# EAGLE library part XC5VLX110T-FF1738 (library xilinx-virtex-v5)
xc5vlx110t_ff1738 edit this description Auto generated by make-symbol-device-package-bsdl.ulp Rev. 21 Source: xc5vlx110t_ff1738.bsd Connect-List generated from XC5VLX110T_FF1738.DEV Variant '' with split-device-symbol.ulp
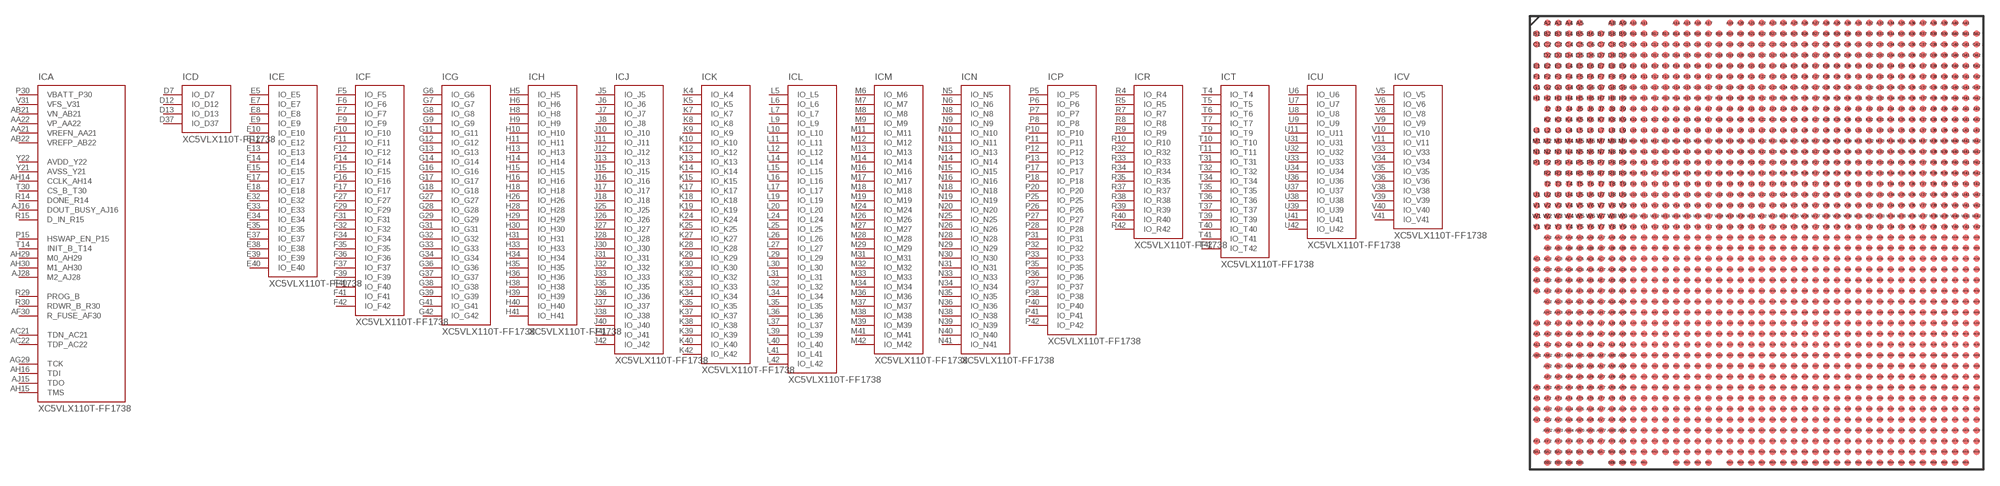
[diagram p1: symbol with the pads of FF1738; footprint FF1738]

Designator prefix IC; gates A=XC5VLX110T_FF1738-CONTROL D=XC5VLX110T_FF1738-IO-D E=XC5VLX110T_FF1738-IO-E F=XC5VLX110T_FF1738-IO-F G=XC5VLX110T_FF1738-IO-G H=XC5VLX110T_FF1738-IO-H J=XC5VLX110T_FF1738-IO-J K=XC5VLX110T_FF1738-IO-K L=XC5VLX110T_FF1738-IO-L M=XC5VLX110T_FF1738-IO-M N=XC5VLX110T_FF1738-IO-N P=XC5VLX110T_FF1738-IO-P R=XC5VLX110T_FF1738-IO-R T=XC5VLX110T_FF1738-IO-T U=XC5VLX110T_FF1738-IO-U V=XC5VLX110T_FF1738-IO-V W=XC5VLX110T_FF1738-IO-W Y=XC5VLX110T_FF1738-IO-Y AA=XC5VLX110T_FF1738-IO-AA AB=XC5VLX110T_FF1738-IO-AB AC=XC5VLX110T_FF1738-IO-AC AD=XC5VLX110T_FF1738-IO-AD AE=XC5VLX110T_FF1738-IO-AE AF=XC5VLX110T_FF1738-IO-AF AG=XC5VLX110T_FF1738-IO-AG AH=XC5VLX110T_FF1738-IO-AH AJ=XC5VLX110T_FF1738-IO-AJ AK=XC5VLX110T_FF1738-IO-AK AL=XC5VLX110T_FF1738-IO-AL AM=XC5VLX110T_FF1738-IO-AM AN=XC5VLX110T_FF1738-IO-AN AP=XC5VLX110T_FF1738-IO-AP AR=XC5VLX110T_FF1738-IO-AR AT=XC5VLX110T_FF1738-IO-AT AU=XC5VLX110T_FF1738-IO-AU AV=XC5VLX110T_FF1738-IO-AV MGTAVTTRX=XC5VLX110T_FF1738-MGTAVTTRX MGREFCLKN=XC5VLX110T_FF1738-MGTREFCLKN MGRX=XC5VLX110T_FF1738-MGTRX MGTTRXN=XC5VLX110T_FF1738-MGTTXN VCCINT=XC5VLX110T_FF1738-VCCINT VCCO=XC5VLX110T_FF1738-VCCO VCCAUX=XC5VLX110T_FF1738-VCCAUX MGTAVCC=XC5VLX110T_FF1738-MGTAVCC MGTAVCCPLL=XC5VLX110T_FF1738-MGTAVCCPLL GND=XC5VLX110T_FF1738-GND NC=XC5VLX110T_FF1738-NOCONNECT

## XC5VLX110T-FF1738 (OC_FARNELL: unknown; OC_NEWARK: unknown)  [FF1738]
A2  MGRX:MGTRXP1_124  pas
A3  MGRX:MGTRXN1_124  pas
A4  MGRX:MGTRXN0_124  pas
A5  MGRX:MGTRXP0_124  pas
A8  NC:NOCONNECT1  pas
A9  NC:NOCONNECT2  pas
A10  NC:NOCONNECT3  pas
A11  NC:NOCONNECT4  pas
A14  NC:NOCONNECT5  pas
A15  NC:NOCONNECT6  pas
A16  NC:NOCONNECT7  pas
A17  NC:NOCONNECT8  pas
A19  GND:GND  pwr
A20  NC:NOCONNECT9  pas
A21  NC:NOCONNECT10  pas
A22  NC:NOCONNECT11  pas
A23  GND:GND  pwr
A24  NC:NOCONNECT12  pas
A25  NC:NOCONNECT13  pas
A26  NC:NOCONNECT14  pas
A27  NC:NOCONNECT15  pas
A28  GND:GND  pwr
A29  NC:NOCONNECT16  pas
A30  NC:NOCONNECT17  pas
A31  NC:NOCONNECT18  pas
A32  NC:NOCONNECT19  pas
A33  GND:GND  pwr
A34  NC:NOCONNECT20  pas
A35  NC:NOCONNECT21  pas
A36  NC:NOCONNECT22  pas
A37  NC:NOCONNECT23  pas
A38  GND:GND  pwr
A39  NC:NOCONNECT24  pas
A40  NC:NOCONNECT25  pas
A41  NC:NOCONNECT26  pas
AA2  MGTTRXN:MGTTXP1_112  pas
AA3  MGTAVTTRX:MGTAVTTTX_1122  pas
AA4  NC:NOCONNECT150  pas
AA5  MGTAVTTRX:MGTAVTTRXC  pas
AA6  AA:IO_AA6
AA7  AA:IO_AA7
AA8  VCCO:VCCO12  pwr
AA9  AA:IO_AA9
AA10  AA:IO_AA10
AA11  AA:IO_AA11
AA12  VCCAUX:VCCAUX  pwr
AA13  GND:GND  pwr
AA14  VCCINT:VCCINT  pwr
AA15  GND:GND  pwr
AA16  VCCINT:VCCINT  pwr
AA17  GND:GND  pwr
AA18  VCCINT:VCCINT  pwr
AA19  GND:GND  pwr
AA20  VCCINT:VCCINT  pwr
AA21  A:VREFN_AA21  pas
AA22  A:VP_AA22  pas
AA23  GND:GND  pwr
AA24  VCCINT:VCCINT  pwr
AA25  GND:GND  pwr
AA26  VCCINT:VCCINT  pwr
AA27  GND:GND  pwr
AA28  VCCINT:VCCINT  pwr
AA29  GND:GND  pwr
AA30  VCCAUX:VCCAUX  pwr
AA31  GND:GND  pwr
AA32  AA:IO_AA32
AA33  GND:GND  pwr
AA34  AA:IO_AA34
AA35  AA:IO_AA35
AA36  AA:IO_AA36
AA37  AA:IO_AA37
AA38  VCCO:VCCO11  pwr
AA39  AA:IO_AA39
AA40  AA:IO_AA40
AA41  AA:IO_AA41
AA42  AA:IO_AA42
AB2  MGTTRXN:MGTTXP0_114  pas
AB3  MGTAVTTRX:MGTAVTTTX_1141  pas
AB4  MGREFCLKN:MGTRREF_112  pas
AB5  GND:GND  pwr
AB6  AB:IO_AB6
AB7  AB:IO_AB7
AB8  AB:IO_AB8
AB9  AB:IO_AB9
AB10  GND:GND  pwr
AB11  AB:IO_AB11
AB12  GND:GND  pwr
AB13  VCCINT:VCCINT  pwr
AB14  GND:GND  pwr
AB15  VCCINT:VCCINT  pwr
AB16  GND:GND  pwr
AB17  VCCINT:VCCINT  pwr
AB18  GND:GND  pwr
AB19  VCCINT:VCCINT  pwr
AB20  GND:GND  pwr
AB21  A:VN_AB21  pas
AB22  A:VREFP_AB22  pas
AB23  VCCINT:VCCINT  pwr
AB24  GND:GND  pwr
AB25  VCCINT:VCCINT  pwr
AB26  GND:GND  pwr
AB27  VCCINT:VCCINT  pwr
AB28  GND:GND  pwr
AB29  VCCINT:VCCINT  pwr
AB30  GND:GND  pwr
AB31  VCCAUX:VCCAUX  pwr
AB32  AB:IO_AB32
AB33  AB:IO_AB33
AB34  AB:IO_AB34
AB35  VCCO:VCCO13  pwr
AB36  AB:IO_AB36
AB37  AB:IO_AB37
AB38  AB:IO_AB38
AB39  AB:IO_AB39
AB40  GND:GND  pwr
AB41  AB:IO_AB41
AB42  AB:IO_AB42
AC1  MGRX:MGTRXP0_114  pas
AC2  MGTTRXN:MGTTXN0_114  pas
AC3  MGTAVTTRX:MGTAVTTRX_114  pas
AC4  GND:GND  pwr
AC5  AC:IO_AC5
AC6  AC:IO_AC6
AC7  GND:GND  pwr
AC8  AC:IO_AC8
AC9  AC:IO_AC9
AC10  AC:IO_AC10
AC11  GND:GND  pwr
AC12  VCCAUX:VCCAUX  pwr
AC13  GND:GND  pwr
AC14  VCCINT:VCCINT  pwr
AC15  GND:GND  pwr
AC16  VCCINT:VCCINT  pwr
AC17  GND:GND  pwr
AC18  VCCINT:VCCINT  pwr
AC19  GND:GND  pwr
AC20  VCCINT:VCCINT  pwr
AC21  A:TDN_AC21  pas
AC22  A:TDP_AC22  pas
AC23  GND:GND  pwr
AC24  VCCINT:VCCINT  pwr
AC25  GND:GND  pwr
AC26  VCCINT:VCCINT  pwr
AC27  GND:GND  pwr
AC28  VCCINT:VCCINT  pwr
AC29  GND:GND  pwr
AC30  VCCAUX:VCCAUX  pwr
AC31  GND:GND  pwr
AC32  GND:GND  pwr
AC33  AC:IO_AC33
AC34  AC:IO_AC34
AC35  AC:IO_AC35
AC36  AC:IO_AC36
AC37  GND:GND  pwr
AC38  AC:IO_AC38
AC39  AC:IO_AC39
AC40  AC:IO_AC40
AC41  AC:IO_AC41
AC42  GND:GND  pwr
AD1  MGRX:MGTRXN0_114  pas
AD2  GND:GND  pwr
AD3  MGREFCLKN:MGTREFCLKN_114  pas
AD4  MGREFCLKN:MGTREFCLKP_114  pas
AD5  AD:IO_AD5
AD6  AD:IO_AD6
AD7  AD:IO_AD7
AD8  AD:IO_AD8
AD9  VCCO:VCCO18  pwr
AD10  AD:IO_AD10
AD11  AD:IO_AD11
AD12  GND:GND  pwr
AD13  VCCINT:VCCINT  pwr
AD14  GND:GND  pwr
AD15  VCCINT:VCCINT  pwr
AD16  GND:GND  pwr
AD17  VCCINT:VCCINT  pwr
AD18  GND:GND  pwr
AD19  VCCINT:VCCINT  pwr
AD20  GND:GND  pwr
AD21  VCCINT:VCCINT  pwr
AD22  GND:GND  pwr
AD23  VCCINT:VCCINT  pwr
AD24  GND:GND  pwr
AD25  VCCINT:VCCINT  pwr
AD26  GND:GND  pwr
AD27  VCCINT:VCCINT  pwr
AD28  GND:GND  pwr
AD29  VCCINT:VCCINT  pwr
AD30  GND:GND  pwr
AD31  VCCAUX:VCCAUX  pwr
AD32  AD:IO_AD32
AD33  AD:IO_AD33
AD34  GND:GND  pwr
AD35  AD:IO_AD35
AD36  AD:IO_AD36
AD37  AD:IO_AD37
AD38  AD:IO_AD38
AD39  VCCO:VCCO13  pwr
AD40  AD:IO_AD40
AD41  AD:IO_AD41
AD42  AD:IO_AD42
AE1  MGRX:MGTRXN1_114  pas
AE2  GND:GND  pwr
AE3  MGTAVCC:MGTAVCC_114  pwr
AE4  MGTAVCC:MGTAVCC_114  pwr
AE5  AE:IO_AE5
AE6  VCCO:VCCO18  pwr
AE7  AE:IO_AE7
AE8  AE:IO_AE8
AE9  AE:IO_AE9
AE10  AE:IO_AE10
AE11  GND:GND  pwr
AE12  VCCAUX:VCCAUX  pwr
AE13  GND:GND  pwr
AE14  VCCINT:VCCINT  pwr
AE15  GND:GND  pwr
AE16  VCCINT:VCCINT  pwr
AE17  GND:GND  pwr
AE18  VCCINT:VCCINT  pwr
AE19  GND:GND  pwr
AE20  VCCINT:VCCINT  pwr
AE21  GND:GND  pwr
AE22  VCCINT:VCCINT  pwr
AE23  GND:GND  pwr
AE24  VCCINT:VCCINT  pwr
AE25  GND:GND  pwr
AE26  VCCINT:VCCINT  pwr
AE27  GND:GND  pwr
AE28  VCCINT:VCCINT  pwr
AE29  GND:GND  pwr
AE30  VCCAUX:VCCAUX  pwr
AE31  GND:GND  pwr
AE32  AE:IO_AE32
AE33  AE:IO_AE33
AE34  AE:IO_AE34
AE35  AE:IO_AE35
AE36  VCCO:VCCO13  pwr
AE37  AE:IO_AE37
AE38  AE:IO_AE38
AE39  AE:IO_AE39
AE40  AE:IO_AE40
AE41  GND:GND  pwr
AE42  AE:IO_AE42
AF1  MGRX:MGTRXP1_114  pas
AF2  MGTTRXN:MGTTXN1_114  pas
AF3  MGTAVCCPLL:MGTAVCCPLL_114  pwr
AF4  GND:GND  pwr
AF5  AF:IO_AF5
AF6  AF:IO_AF6
AF7  AF:IO_AF7
AF8  GND:GND  pwr
AF9  AF:IO_AF9
AF10  AF:IO_AF10
AF11  AF:IO_AF11
AF12  AF:IO_AF12
AF13  VCCAUX:VCCAUX  pwr
AF14  GND:GND  pwr
AF15  VCCINT:VCCINT  pwr
AF16  GND:GND  pwr
AF17  VCCINT:VCCINT  pwr
AF18  GND:GND  pwr
AF19  VCCINT:VCCINT  pwr
AF20  GND:GND  pwr
AF21  VCCINT:VCCINT  pwr
AF22  GND:GND  pwr
AF23  VCCINT:VCCINT  pwr
AF24  GND:GND  pwr
AF25  VCCINT:VCCINT  pwr
AF26  GND:GND  pwr
AF27  VCCINT:VCCINT  pwr
AF28  GND:GND  pwr
AF29  VCCAUX:VCCAUX  pwr
AF30  A:R_FUSE_AF30  pas
AF31  AF:IO_AF31
AF32  AF:IO_AF32
AF33  GND:GND  pwr
AF34  AF:IO_AF34
AF35  AF:IO_AF35
AF36  AF:IO_AF36
AF37  AF:IO_AF37
AF38  GND:GND  pwr
AF39  AF:IO_AF39
AF40  AF:IO_AF40
AF41  AF:IO_AF41
AF42  AF:IO_AF42
AG2  MGTTRXN:MGTTXP1_114  pas
AG3  MGTAVTTRX:MGTAVTTTX_1142  pas
AG4  AG:IO_AG4
AG5  GND:GND  pwr
AG6  AG:IO_AG6
AG7  AG:IO_AG7
AG8  AG:IO_AG8
AG9  AG:IO_AG9
AG10  VCCO:VCCO18  pwr
AG11  AG:IO_AG11
AG12  AG:IO_AG12
AG13  GND:GND  pwr
AG14  VCCINT:VCCINT  pwr
AG15  GND:GND  pwr
AG16  VCCINT:VCCINT  pwr
AG17  GND:GND  pwr
AG18  VCCINT:VCCINT  pwr
AG19  GND:GND  pwr
AG20  VCCINT:VCCINT  pwr
AG21  GND:GND  pwr
AG22  VCCINT:VCCINT  pwr
AG23  GND:GND  pwr
AG24  VCCINT:VCCINT  pwr
AG25  GND:GND  pwr
AG26  VCCINT:VCCINT  pwr
AG27  GND:GND  pwr
AG28  VCCINT:VCCINT  pwr
AG29  A:TCK  in
AG30  VCCO:VCCO0  pwr
AG31  AG:IO_AG31
AG32  AG:IO_AG32
AG33  AG:IO_AG33
AG34  AG:IO_AG34
AG35  GND:GND  pwr
AG36  AG:IO_AG36
AG37  AG:IO_AG37
AG38  AG:IO_AG38
AG39  AG:IO_AG39
AG40  VCCO:VCCO17  pwr
AG41  AG:IO_AG41
AG42  AG:IO_AG42
AH2  MGTTRXN:MGTTXP0_118  pas
AH3  MGTAVTTRX:MGTAVTTTX_1181  pas
AH4  AH:IO_AH4
AH5  AH:IO_AH5
AH6  AH:IO_AH6
AH7  VCCO:VCCO26  pwr
AH8  AH:IO_AH8
AH9  AH:IO_AH9
AH10  AH:IO_AH10
AH11  AH:IO_AH11
AH12  GND:GND  pwr
AH13  VCCAUX:VCCAUX  pwr
AH14  A:CCLK_AH14
AH15  A:TMS  in
AH16  A:TDI  in
AH17  VCCINT:VCCINT  pwr
AH18  GND:GND  pwr
AH19  VCCINT:VCCINT  pwr
AH20  GND:GND  pwr
AH21  VCCINT:VCCINT  pwr
AH22  GND:GND  pwr
AH23  VCCINT:VCCINT  pwr
AH24  GND:GND  pwr
AH25  VCCINT:VCCINT  pwr
AH26  GND:GND  pwr
AH27  VCCINT:VCCINT  pwr
AH28  GND:GND  pwr
AH29  A:M0_AH29  in
AH30  A:M1_AH30  in
AH31  AH:IO_AH31
AH32  GND:GND  pwr
AH33  AH:IO_AH33
AH34  AH:IO_AH34
AH35  AH:IO_AH35
AH36  AH:IO_AH36
AH37  VCCO:VCCO17  pwr
AH38  AH:IO_AH38
AH39  AH:IO_AH39
AH40  AH:IO_AH40
AH41  AH:IO_AH41
AH42  GND:GND  pwr
AJ1  MGRX:MGTRXP0_118  pas
AJ2  MGTTRXN:MGTTXN0_118  pas
AJ3  MGTAVTTRX:MGTAVTTRX_118  pas
AJ4  GND:GND  pwr
AJ5  AJ:IO_AJ5
AJ6  AJ:IO_AJ6
AJ7  AJ:IO_AJ7
AJ8  AJ:IO_AJ8
AJ9  GND:GND  pwr
AJ10  AJ:IO_AJ10
AJ11  AJ:IO_AJ11
AJ12  VCCAUX:VCCAUX  pwr
AJ13  GND:GND  pwr
AJ14  GND:GND  pwr
AJ15  A:TDO  out
AJ16  A:DOUT_BUSY_AJ16  out
AJ17  GND:GND  pwr
AJ18  VCCINT:VCCINT  pwr
AJ19  GND:GND  pwr
AJ20  VCCINT:VCCINT  pwr
AJ21  NC:NOCONNECT151  pas
AJ22  NC:NOCONNECT152  pas
AJ23  GND:GND  pwr
AJ24  VCCINT:VCCINT  pwr
AJ25  GND:GND  pwr
AJ26  AJ:IO_AJ26
AJ27  GND:GND  pwr
AJ28  A:M2_AJ28  in
AJ29  GND:GND  pwr
AJ30  AJ:IO_AJ30
AJ31  AJ:IO_AJ31
AJ32  AJ:IO_AJ32
AJ33  AJ:IO_AJ33
AJ34  VCCO:VCCO21  pwr
AJ35  AJ:IO_AJ35
AJ36  AJ:IO_AJ36
AJ37  AJ:IO_AJ37
AJ38  AJ:IO_AJ38
AJ39  GND:GND  pwr
AJ40  AJ:IO_AJ40
AJ41  AJ:IO_AJ41
AJ42  AJ:IO_AJ42
AK1  MGRX:MGTRXN0_118  pas
AK2  GND:GND  pwr
AK3  MGREFCLKN:MGTREFCLKN_118  pas
AK4  MGREFCLKN:MGTREFCLKP_118  pas
AK5  AK:IO_AK5
AK6  GND:GND  pwr
AK7  AK:IO_AK7
AK8  AK:IO_AK8
AK9  AK:IO_AK9
AK10  AK:IO_AK10
AK11  VCCO:VCCO26  pwr
AK12  AK:IO_AK12
AK13  AK:IO_AK13
AK14  AK:IO_AK14
AK15  AK:IO_AK15
AK16  GND:GND  pwr
AK17  AK:IO_AK17
AK18  AK:IO_AK18
AK19  AK:IO_AK19
AK20  NC:NOCONNECT153  pas
AK21  GND:GND  pwr
AK22  NC:NOCONNECT154  pas
AK23  NC:NOCONNECT155  pas
AK24  AK:IO_AK24
AK25  AK:IO_AK25
AK26  GND:GND  pwr
AK27  AK:IO_AK27
AK28  AK:IO_AK28
AK29  AK:IO_AK29
AK30  AK:IO_AK30
AK31  GND:GND  pwr
AK32  AK:IO_AK32
AK33  AK:IO_AK33
AK34  AK:IO_AK34
AK35  AK:IO_AK35
AK36  GND:GND  pwr
AK37  AK:IO_AK37
AK38  AK:IO_AK38
AK39  AK:IO_AK39
AK40  AK:IO_AK40
AK41  VCCO:VCCO17  pwr
AK42  AK:IO_AK42
AL1  MGRX:MGTRXN1_118  pas
AL2  GND:GND  pwr
AL3  MGTAVCC:MGTAVCC_118  pwr
AL4  MGTAVCC:MGTAVCC_118  pwr
AL5  AL:IO_AL5
AL6  AL:IO_AL6
AL7  AL:IO_AL7
AL8  VCCO:VCCO26  pwr
AL9  AL:IO_AL9
AL10  AL:IO_AL10
AL11  NC:NOCONNECT156  pas
AL12  NC:NOCONNECT157  pas
AL13  GND:GND  pwr
AL14  AL:IO_AL14
AL15  AL:IO_AL15
AL16  AL:IO_AL16
AL17  AL:IO_AL17
AL18  GND:GND  pwr
AL19  AL:IO_AL19
AL20  NC:NOCONNECT158  pas
AL21  NC:NOCONNECT159  pas
AL22  NC:NOCONNECT160  pas
AL23  GND:GND  pwr
AL24  AL:IO_AL24
AL25  AL:IO_AL25
AL26  AL:IO_AL26
AL27  AL:IO_AL27
AL28  VCCO:VCCO0  pwr
AL29  AL:IO_AL29
AL30  AL:IO_AL30
AL31  AL:IO_AL31
AL32  AL:IO_AL32
AL33  GND:GND  pwr
AL34  AL:IO_AL34
AL35  AL:IO_AL35
AL36  AL:IO_AL36
AL37  AL:IO_AL37
AL38  VCCO:VCCO21  pwr
AL39  AL:IO_AL39
AL40  AL:IO_AL40
AL41  AL:IO_AL41
AL42  AL:IO_AL42
AM1  MGRX:MGTRXP1_118  pas
AM2  MGTTRXN:MGTTXN1_118  pas
AM3  MGTAVCCPLL:MGTAVCCPLL_118  pwr
AM4  GND:GND  pwr
AM5  GND:GND  pwr
AM6  AM:IO_AM6
AM7  AM:IO_AM7
AM8  AM:IO_AM8
AM9  AM:IO_AM9
AM10  GND:GND  pwr
AM11  NC:NOCONNECT161  pas
AM12  NC:NOCONNECT162  pas
AM13  AM:IO_AM13
AM14  AM:IO_AM14
AM15  GND:GND  pwr
AM16  AM:IO_AM16
AM17  AM:IO_AM17
AM18  AM:IO_AM18
AM19  AM:IO_AM19
AM20  GND:GND  pwr
AM21  NC:NOCONNECT163  pas
AM22  NC:NOCONNECT164  pas
AM23  NC:NOCONNECT165  pas
AM24  AM:IO_AM24
AM25  GND:GND  pwr
AM26  AM:IO_AM26
AM27  AM:IO_AM27
AM28  AM:IO_AM28
AM29  AM:IO_AM29
AM30  GND:GND  pwr
AM31  AM:IO_AM31
AM32  AM:IO_AM32
AM33  AM:IO_AM33
AM34  AM:IO_AM34
AM35  VCCO:VCCO21  pwr
AM36  AM:IO_AM36
AM37  AM:IO_AM37
AM38  AM:IO_AM38
AM39  AM:IO_AM39
AM40  GND:GND  pwr
AM41  AM:IO_AM41
AM42  AM:IO_AM42
AN2  MGTTRXN:MGTTXP1_118  pas
AN3  MGTAVTTRX:MGTAVTTTX_1182  pas
AN4  AN:IO_AN4
AN5  AN:IO_AN5
AN6  AN:IO_AN6
AN7  GND:GND  pwr
AN8  AN:IO_AN8
AN9  AN:IO_AN9
AN10  NC:NOCONNECT166  pas
AN11  NC:NOCONNECT167  pas
AN12  GND:GND  pwr
AN13  AN:IO_AN13
AN14  AN:IO_AN14
AN15  AN:IO_AN15
AN16  AN:IO_AN16
AN17  GND:GND  pwr
AN18  AN:IO_AN18
AN19  AN:IO_AN19
AN20  AN:IO_AN20
AN21  NC:NOCONNECT168  pas
AN22  GND:GND  pwr
AN23  NC:NOCONNECT169  pas
AN24  AN:IO_AN24
AN25  AN:IO_AN25
AN26  AN:IO_AN26
AN27  GND:GND  pwr
AN28  AN:IO_AN28
AN29  AN:IO_AN29
AN30  AN:IO_AN30
AN31  AN:IO_AN31
AN32  GND:GND  pwr
AN33  AN:IO_AN33
AN34  AN:IO_AN34
AN35  AN:IO_AN35
AN36  AN:IO_AN36
AN37  GND:GND  pwr
AN38  AN:IO_AN38
AN39  AN:IO_AN39
AN40  AN:IO_AN40
AN41  AN:IO_AN41
AN42  GND:GND  pwr
AP2  MGTTRXN:MGTTXP0_122  pas
AP3  MGTAVTTRX:MGTAVTTTX_1221  pas
AP4  GND:GND  pwr
AP5  AP:IO_AP5
AP6  AP:IO_AP6
AP7  AP:IO_AP7
AP8  AP:IO_AP8
AP9  VCCO:VCCO34  pwr
AP10  NC:NOCONNECT170  pas
AP11  NC:NOCONNECT171  pas
AP12  NC:NOCONNECT172  pas
AP13  AP:IO_AP13
AP14  GND:GND  pwr
AP15  AP:IO_AP15
AP16  AP:IO_AP16
AP17  AP:IO_AP17
AP18  AP:IO_AP18
AP19  VCCO:VCCO8  pwr
AP20  NC:NOCONNECT173  pas
AP21  NC:NOCONNECT174  pas
AP22  NC:NOCONNECT175  pas
AP23  NC:NOCONNECT176  pas
AP24  GND:GND  pwr
AP25  AP:IO_AP25
AP26  AP:IO_AP26
AP27  AP:IO_AP27
AP28  AP:IO_AP28
AP29  GND:GND  pwr
AP30  AP:IO_AP30
AP31  AP:IO_AP31
AP32  AP:IO_AP32
AP33  AP:IO_AP33
AP34  GND:GND  pwr
AP35  AP:IO_AP35
AP36  AP:IO_AP36
AP37  AP:IO_AP37
AP38  AP:IO_AP38
AP39  VCCO:VCCO25  pwr
AP40  AP:IO_AP40
AP41  AP:IO_AP41
AP42  AP:IO_AP42
AR1  MGRX:MGTRXP0_122  pas
AR2  MGTTRXN:MGTTXN0_122  pas
AR3  MGTAVTTRX:MGTAVTTRX_122  pas
AR4  GND:GND  pwr
AR5  AR:IO_AR5
AR6  GND:GND  pwr
AR7  AR:IO_AR7
AR8  AR:IO_AR8
AR9  NC:NOCONNECT177  pas
AR10  NC:NOCONNECT178  pas
AR11  GND:GND  pwr
AR12  NC:NOCONNECT179  pas
AR13  NC:NOCONNECT180  pas
AR14  AR:IO_AR14
AR15  AR:IO_AR15
AR16  VCCO:VCCO4  pwr
AR17  AR:IO_AR17
AR18  AR:IO_AR18
AR19  AR:IO_AR19
AR20  NC:NOCONNECT181  pas
AR21  GND:GND  pwr
AR22  NC:NOCONNECT182  pas
AR23  NC:NOCONNECT183  pas
AR24  NC:NOCONNECT184  pas
AR25  NC:NOCONNECT185  pas
AR26  VCCO:VCCO2  pwr
AR27  AR:IO_AR27
AR28  AR:IO_AR28
AR29  AR:IO_AR29
AR30  AR:IO_AR30
AR31  GND:GND  pwr
AR32  AR:IO_AR32
AR33  AR:IO_AR33
AR34  AR:IO_AR34
AR35  AR:IO_AR35
AR36  VCCO:VCCO25  pwr
AR37  AR:IO_AR37
AR38  AR:IO_AR38
AR39  AR:IO_AR39
AR40  AR:IO_AR40
AR41  GND:GND  pwr
AR42  AR:IO_AR42
AT1  MGRX:MGTRXN0_122  pas
AT2  GND:GND  pwr
AT3  MGREFCLKN:MGTREFCLKN_122  pas
AT4  MGREFCLKN:MGTREFCLKP_122  pas
AT5  AT:IO_AT5
AT6  AT:IO_AT6
AT7  AT:IO_AT7
AT8  GND:GND  pwr
AT9  NC:NOCONNECT186  pas
AT10  NC:NOCONNECT187  pas
AT11  NC:NOCONNECT188  pas
AT12  NC:NOCONNECT189  pas
AT13  VCCO:VCCO4  pwr
AT14  AT:IO_AT14
AT15  AT:IO_AT15
AT16  AT:IO_AT16
AT17  AT:IO_AT17
AT18  GND:GND  pwr
AT19  AT:IO_AT19
AT20  NC:NOCONNECT190  pas
AT21  NC:NOCONNECT191  pas
AT22  NC:NOCONNECT192  pas
AT23  VCCO:VCCO6  pwr
AT24  NC:NOCONNECT193  pas
AT25  NC:NOCONNECT194  pas
AT26  AT:IO_AT26
AT27  AT:IO_AT27
AT28  GND:GND  pwr
AT29  AT:IO_AT29
AT30  AT:IO_AT30
AT31  AT:IO_AT31
AT32  AT:IO_AT32
AT33  VCCO:VCCO29  pwr
AT34  AT:IO_AT34
AT35  AT:IO_AT35
AT36  AT:IO_AT36
AT37  AT:IO_AT37
AT38  GND:GND  pwr
AT39  AT:IO_AT39
AT40  AT:IO_AT40
AT41  AT:IO_AT41
AT42  AT:IO_AT42
AU1  MGRX:MGTRXN1_122  pas
AU2  GND:GND  pwr
AU3  MGTAVCC:MGTAVCC_122  pwr
AU4  MGTAVCC:MGTAVCC_122  pwr
AU5  GND:GND  pwr
AU6  AU:IO_AU6
AU7  NC:NOCONNECT195  pas
AU8  NC:NOCONNECT196  pas
AU9  NC:NOCONNECT197  pas
AU10  VCCO:VCCO34  pwr
AU11  NC:NOCONNECT198  pas
AU12  NC:NOCONNECT199  pas
AU13  NC:NOCONNECT200  pas
AU14  NC:NOCONNECT201  pas
AU15  GND:GND  pwr
AU16  NC:NOCONNECT202  pas
AU17  NC:NOCONNECT203  pas
AU18  NC:NOCONNECT204  pas
AU19  NC:NOCONNECT205  pas
AU20  VCCO:VCCO8  pwr
AU21  NC:NOCONNECT206  pas
AU22  NC:NOCONNECT207  pas
AU23  NC:NOCONNECT208  pas
AU24  NC:NOCONNECT209  pas
AU25  GND:GND  pwr
AU26  NC:NOCONNECT210  pas
AU27  NC:NOCONNECT211  pas
AU28  AU:IO_AU28
AU29  AU:IO_AU29
AU30  VCCO:VCCO33  pwr
AU31  AU:IO_AU31
AU32  AU:IO_AU32
AU33  AU:IO_AU33
AU34  AU:IO_AU34
AU35  GND:GND  pwr
AU36  AU:IO_AU36
AU37  AU:IO_AU37
AU38  AU:IO_AU38
AU39  AU:IO_AU39
AU40  VCCO:VCCO25  pwr
AU41  AU:IO_AU41
AU42  AU:IO_AU42
AV1  MGRX:MGTRXP1_122  pas
AV2  MGTTRXN:MGTTXN1_122  pas
AV3  MGTAVCCPLL:MGTAVCCPLL_122  pwr
AV4  GND:GND  pwr
AV5  AV:IO_AV5
AV6  AV:IO_AV6
AV7  VCCO:VCCO34  pwr
AV8  NC:NOCONNECT212  pas
AV9  NC:NOCONNECT213  pas
AV10  NC:NOCONNECT214  pas
AV11  NC:NOCONNECT215  pas
AV12  GND:GND  pwr
AV13  NC:NOCONNECT216  pas
AV14  NC:NOCONNECT217  pas
AV15  NC:NOCONNECT218  pas
AV16  NC:NOCONNECT219  pas
AV17  VCCO:VCCO8  pwr
AV18  NC:NOCONNECT220  pas
AV19  NC:NOCONNECT221  pas
AV20  NC:NOCONNECT222  pas
AV21  NC:NOCONNECT223  pas
AV22  GND:GND  pwr
AV23  NC:NOCONNECT224  pas
AV24  NC:NOCONNECT225  pas
AV25  NC:NOCONNECT226  pas
AV26  NC:NOCONNECT227  pas
AV27  VCCO:VCCO2  pwr
AV28  NC:NOCONNECT228  pas
AV29  NC:NOCONNECT229  pas
AV30  NC:NOCONNECT230  pas
AV31  AV:IO_AV31
AV32  GND:GND  pwr
AV33  AV:IO_AV33
AV34  AV:IO_AV34
AV35  AV:IO_AV35
AV36  AV:IO_AV36
AV37  VCCO:VCCO29  pwr
AV38  AV:IO_AV38
AV39  AV:IO_AV39
AV40  AV:IO_AV40
AV41  AV:IO_AV41
AV42  GND:GND  pwr
AW2  MGTTRXN:MGTTXP1_122  pas
AW3  MGTAVTTRX:MGTAVTTTX_1222  pas
AW4  MGREFCLKN:MGTREFCLKP_126  pas
AW5  MGTAVCC:MGTAVCC_126  pwr
AW6  GND:GND  pwr
AW7  NC:NOCONNECT231  pas
AW8  GND:GND  pwr
AW9  NC:NOCONNECT232  pas
AW10  MGTAVCC:MGTAVCC_130  pwr
AW11  GND:GND  pwr
AW12  NC:NOCONNECT233  pas
AW13  NC:NOCONNECT234  pas
AW14  GND:GND  pwr
AW15  NC:NOCONNECT235  pas
AW16  MGTAVCC:MGTAVCC_134  pwr
AW17  GND:GND  pwr
AW18  NC:NOCONNECT236  pas
AW19  GND:GND  pwr
AW20  NC:NOCONNECT237  pas
AW21  NC:NOCONNECT238  pas
AW22  NC:NOCONNECT239  pas
AW23  NC:NOCONNECT240  pas
AW24  VCCO:VCCO6  pwr
AW25  NC:NOCONNECT241  pas
AW26  NC:NOCONNECT242  pas
AW27  NC:NOCONNECT243  pas
AW28  NC:NOCONNECT244  pas
AW29  GND:GND  pwr
AW30  NC:NOCONNECT245  pas
AW31  NC:NOCONNECT246  pas
AW32  NC:NOCONNECT247  pas
AW33  NC:NOCONNECT248  pas
AW34  VCCO:VCCO29  pwr
AW35  NC:NOCONNECT249  pas
AW36  NC:NOCONNECT250  pas
AW37  NC:NOCONNECT251  pas
AW38  NC:NOCONNECT252  pas
AW39  GND:GND  pwr
AW40  NC:NOCONNECT253  pas
AW41  NC:NOCONNECT254  pas
AW42  NC:NOCONNECT255  pas
AY1  MGTAVTTRX:MGTAVTTTX_1261  pas
AY2  MGTAVTTRX:MGTAVTTRX_126  pas
AY3  MGTAVCC:MGTAVCC_126  pwr
AY4  MGREFCLKN:MGTREFCLKN_126  pas
AY5  MGTAVCCPLL:MGTAVCCPLL_126  pwr
AY6  MGTAVTTRX:MGTAVTTTX_1262  pas
AY7  NC:NOCONNECT256  pas
AY8  NC:NOCONNECT257  pas
AY9  NC:NOCONNECT258  pas
AY10  MGTAVCC:MGTAVCC_130  pwr
AY11  NC:NOCONNECT259  pas
AY12  NC:NOCONNECT260  pas
AY13  NC:NOCONNECT261  pas
AY14  NC:NOCONNECT262  pas
AY15  NC:NOCONNECT263  pas
AY16  MGTAVCC:MGTAVCC_134  pwr
AY17  NC:NOCONNECT264  pas
AY18  NC:NOCONNECT265  pas
AY19  NC:NOCONNECT266  pas
AY20  NC:NOCONNECT267  pas
AY21  VCCO:VCCO6  pwr
AY22  NC:NOCONNECT268  pas
AY23  NC:NOCONNECT269  pas
AY24  NC:NOCONNECT270  pas
AY25  NC:NOCONNECT271  pas
AY26  GND:GND  pwr
AY27  NC:NOCONNECT272  pas
AY28  NC:NOCONNECT273  pas
AY29  NC:NOCONNECT274  pas
AY30  NC:NOCONNECT275  pas
AY31  VCCO:VCCO33  pwr
AY32  NC:NOCONNECT276  pas
AY33  NC:NOCONNECT277  pas
AY34  NC:NOCONNECT278  pas
AY35  NC:NOCONNECT279  pas
AY36  GND:GND  pwr
AY37  NC:NOCONNECT280  pas
AY38  NC:NOCONNECT281  pas
AY39  NC:NOCONNECT282  pas
AY40  NC:NOCONNECT283  pas
AY41  GND:GND  pwr
AY42  NC:NOCONNECT284  pas
B1  MGTTRXN:MGTTXP1_124  pas
B2  MGTTRXN:MGTTXN1_124  pas
B3  GND:GND  pwr
B4  GND:GND  pwr
B5  MGTTRXN:MGTTXN0_124  pas
B6  MGTTRXN:MGTTXP0_124  pas
B7  NC:NOCONNECT27  pas
B8  NC:NOCONNECT28  pas
B9  GND:GND  pwr
B10  GND:GND  pwr
B11  NC:NOCONNECT29  pas
B12  NC:NOCONNECT30  pas
B13  NC:NOCONNECT31  pas
B14  NC:NOCONNECT32  pas
B15  GND:GND  pwr
B16  GND:GND  pwr
B17  NC:NOCONNECT33  pas
B18  NC:NOCONNECT34  pas
B19  GND:GND  pwr
B20  GND:GND  pwr
B21  NC:NOCONNECT35  pas
B22  NC:NOCONNECT36  pas
B23  NC:NOCONNECT37  pas
B24  NC:NOCONNECT38  pas
B25  VCCO:VCCO5  pwr
B26  NC:NOCONNECT39  pas
B27  NC:NOCONNECT40  pas
B28  NC:NOCONNECT41  pas
B29  NC:NOCONNECT42  pas
B30  GND:GND  pwr
B31  NC:NOCONNECT43  pas
B32  NC:NOCONNECT44  pas
B33  NC:NOCONNECT45  pas
B34  NC:NOCONNECT46  pas
B35  VCCO:VCCO27  pwr
B36  NC:NOCONNECT47  pas
B37  NC:NOCONNECT48  pas
B38  NC:NOCONNECT49  pas
B39  NC:NOCONNECT50  pas
B40  GND:GND  pwr
B41  NC:NOCONNECT51  pas
B42  NC:NOCONNECT52  pas
BA1  MGTTRXN:MGTTXP0_126  pas
BA2  MGTTRXN:MGTTXN0_126  pas
BA3  GND:GND  pwr
BA4  GND:GND  pwr
BA5  MGTTRXN:MGTTXN1_126  pas
BA6  MGTTRXN:MGTTXP1_126  pas
BA7  NC:NOCONNECT285  pas
BA8  NC:NOCONNECT286  pas
BA9  GND:GND  pwr
BA10  GND:GND  pwr
BA11  NC:NOCONNECT287  pas
BA12  NC:NOCONNECT288  pas
BA13  NC:NOCONNECT289  pas
BA14  NC:NOCONNECT290  pas
BA15  GND:GND  pwr
BA16  GND:GND  pwr
BA17  NC:NOCONNECT291  pas
BA18  NC:NOCONNECT292  pas
BA19  NC:NOCONNECT293  pas
BA20  NC:NOCONNECT294  pas
BA21  NC:NOCONNECT295  pas
BA22  NC:NOCONNECT296  pas
BA23  GND:GND  pwr
BA24  NC:NOCONNECT297  pas
BA25  NC:NOCONNECT298  pas
BA26  NC:NOCONNECT299  pas
BA27  NC:NOCONNECT300  pas
BA28  VCCO:VCCO33  pwr
BA29  NC:NOCONNECT301  pas
BA30  NC:NOCONNECT302  pas
BA31  NC:NOCONNECT303  pas
BA32  NC:NOCONNECT304  pas
BA33  GND:GND  pwr
BA34  NC:NOCONNECT305  pas
BA35  NC:NOCONNECT306  pas
BA36  NC:NOCONNECT307  pas
BA37  NC:NOCONNECT308  pas
BA38  GND:GND  pwr
BA39  NC:NOCONNECT309  pas
BA40  NC:NOCONNECT310  pas
BA41  NC:NOCONNECT311  pas
BA42  NC:NOCONNECT312  pas
BB2  MGRX:MGTRXP0_126  pas
BB3  MGRX:MGTRXN0_126  pas
BB4  MGRX:MGTRXN1_126  pas
BB5  MGRX:MGTRXP1_126  pas
BB8  NC:NOCONNECT313  pas
BB9  NC:NOCONNECT314  pas
BB10  NC:NOCONNECT315  pas
BB11  NC:NOCONNECT316  pas
BB14  NC:NOCONNECT317  pas
BB15  NC:NOCONNECT318  pas
BB16  NC:NOCONNECT319  pas
BB17  NC:NOCONNECT320  pas
BB19  GND:GND  pwr
BB20  NC:NOCONNECT321  pas
BB21  NC:NOCONNECT322  pas
BB22  NC:NOCONNECT323  pas
BB23  NC:NOCONNECT324  pas
BB24  NC:NOCONNECT325  pas
BB25  GND:GND  pwr
BB26  NC:NOCONNECT326  pas
BB27  NC:NOCONNECT327  pas
BB28  NC:NOCONNECT328  pas
BB29  NC:NOCONNECT329  pas
BB30  GND:GND  pwr
BB31  NC:NOCONNECT330  pas
BB32  NC:NOCONNECT331  pas
BB33  NC:NOCONNECT332  pas
BB34  NC:NOCONNECT333  pas
BB35  GND:GND  pwr
BB36  NC:NOCONNECT334  pas
BB37  NC:NOCONNECT335  pas
BB38  NC:NOCONNECT336  pas
BB39  NC:NOCONNECT337  pas
BB40  GND:GND  pwr
BB41  NC:NOCONNECT338  pas
C1  MGTAVTTRX:MGTAVTTTX_1241  pas
C2  MGTAVCCPLL:MGTAVCCPLL_124  pwr
C3  MGREFCLKN:MGTREFCLKN_124  pas
C4  MGREFCLKN:MGTREFCLKP_124  pas
C5  MGTAVTTRX:MGTAVTTRX_124  pas
C6  MGTAVTTRX:MGTAVTTTX_1242  pas
C7  NC:NOCONNECT53  pas
C8  NC:NOCONNECT54  pas
C9  MGTAVCC:MGTAVCC_128  pwr
C10  NC:NOCONNECT55  pas
C11  NC:NOCONNECT56  pas
C12  NC:NOCONNECT57  pas
C13  NC:NOCONNECT58  pas
C14  NC:NOCONNECT59  pas
C15  MGTAVCC:MGTAVCC_132  pwr
C16  NC:NOCONNECT60  pas
C17  NC:NOCONNECT61  pas
C18  NC:NOCONNECT62  pas
C19  GND:GND  pwr
C20  NC:NOCONNECT63  pas
C21  NC:NOCONNECT64  pas
C22  VCCO:VCCO5  pwr
C23  NC:NOCONNECT65  pas
C24  NC:NOCONNECT66  pas
C25  NC:NOCONNECT67  pas
C26  NC:NOCONNECT68  pas
C27  GND:GND  pwr
C28  NC:NOCONNECT69  pas
C29  NC:NOCONNECT70  pas
C30  NC:NOCONNECT71  pas
C31  NC:NOCONNECT72  pas
C32  VCCO:VCCO31  pwr
C33  NC:NOCONNECT73  pas
C34  NC:NOCONNECT74  pas
C35  NC:NOCONNECT75  pas
C36  NC:NOCONNECT76  pas
C37  GND:GND  pwr
C38  NC:NOCONNECT77  pas
C39  NC:NOCONNECT78  pas
C40  NC:NOCONNECT79  pas
C41  NC:NOCONNECT80  pas
C42  GND:GND  pwr
D2  MGTTRXN:MGTTXP0_120  pas
D3  MGTAVTTRX:MGTAVTTTX_1201  pas
D4  MGTAVCC:MGTAVCC_124  pwr
D5  MGTAVCC:MGTAVCC_124  pwr
D6  GND:GND  pwr
D7  D:IO_D7
D8  GND:GND  pwr
D9  MGTAVCC:MGTAVCC_128  pwr
D10  NC:NOCONNECT81  pas
D11  GND:GND  pwr
D12  D:IO_D12
D13  D:IO_D13
D14  GND:GND  pwr
D15  MGTAVCC:MGTAVCC_132  pwr
D16  NC:NOCONNECT82  pas
D17  GND:GND  pwr
D18  NC:NOCONNECT83  pas
D19  VCCO:VCCO7  pwr
D20  NC:NOCONNECT84  pas
D21  NC:NOCONNECT85  pas
D22  NC:NOCONNECT86  pas
D23  NC:NOCONNECT87  pas
D24  GND:GND  pwr
D25  NC:NOCONNECT88  pas
D26  NC:NOCONNECT89  pas
D27  NC:NOCONNECT90  pas
D28  NC:NOCONNECT91  pas
D29  VCCO:VCCO31  pwr
D30  NC:NOCONNECT92  pas
D31  NC:NOCONNECT93  pas
D32  NC:NOCONNECT94  pas
D33  NC:NOCONNECT95  pas
D34  GND:GND  pwr
D35  NC:NOCONNECT96  pas
D36  NC:NOCONNECT97  pas
D37  D:IO_D37
D38  NC:NOCONNECT98  pas
D39  VCCO:VCCO23  pwr
D40  NC:NOCONNECT99  pas
D41  NC:NOCONNECT100  pas
D42  NC:NOCONNECT101  pas
E1  MGRX:MGTRXP0_120  pas
E2  MGTTRXN:MGTTXN0_120  pas
E3  MGTAVTTRX:MGTAVTTRX_120  pas
E4  GND:GND  pwr
E5  E:IO_E5
E6  VCCO:VCCO24  pwr
E7  E:IO_E7
E8  E:IO_E8
E9  E:IO_E9
E10  E:IO_E10
E11  GND:GND  pwr
E12  E:IO_E12
E13  E:IO_E13
E14  E:IO_E14
E15  E:IO_E15
E16  GND:GND  pwr
E17  E:IO_E17
E18  E:IO_E18
E19  NC:NOCONNECT102  pas
E20  NC:NOCONNECT103  pas
E21  GND:GND  pwr
E22  NC:NOCONNECT104  pas
E23  NC:NOCONNECT105  pas
E24  NC:NOCONNECT106  pas
E25  NC:NOCONNECT107  pas
E26  VCCO:VCCO3  pwr
E27  NC:NOCONNECT108  pas
E28  NC:NOCONNECT109  pas
E29  NC:NOCONNECT110  pas
E30  NC:NOCONNECT111  pas
E31  GND:GND  pwr
E32  E:IO_E32
E33  E:IO_E33
E34  E:IO_E34
E35  E:IO_E35
E36  VCCO:VCCO23  pwr
E37  E:IO_E37
E38  E:IO_E38
E39  E:IO_E39
E40  E:IO_E40
E41  GND:GND  pwr
E42  NC:NOCONNECT112  pas
F1  MGRX:MGTRXN0_120  pas
F2  GND:GND  pwr
F3  MGREFCLKN:MGTREFCLKN_120  pas
F4  MGREFCLKN:MGTREFCLKP_120  pas
F5  F:IO_F5
F6  F:IO_F6
F7  F:IO_F7
F8  GND:GND  pwr
F9  F:IO_F9
F10  F:IO_F10
F11  F:IO_F11
F12  F:IO_F12
F13  VCCO:VCCO1  pwr
F14  F:IO_F14
F15  F:IO_F15
F16  F:IO_F16
F17  F:IO_F17
F18  GND:GND  pwr
F19  NC:NOCONNECT113  pas
F20  NC:NOCONNECT114  pas
F21  NC:NOCONNECT115  pas
F22  NC:NOCONNECT116  pas
F23  VCCO:VCCO5  pwr
F24  NC:NOCONNECT117  pas
F25  NC:NOCONNECT118  pas
F26  NC:NOCONNECT119  pas
F27  F:IO_F27
F28  GND:GND  pwr
F29  F:IO_F29
F30  NC:NOCONNECT120  pas
F31  F:IO_F31
F32  F:IO_F32
F33  VCCO:VCCO27  pwr
F34  F:IO_F34
F35  F:IO_F35
F36  F:IO_F36
F37  F:IO_F37
F38  GND:GND  pwr
F39  F:IO_F39
F40  F:IO_F40
F41  F:IO_F41
F42  F:IO_F42
G1  MGRX:MGTRXN1_120  pas
G2  GND:GND  pwr
G3  MGTAVCC:MGTAVCC_120  pwr
G4  MGTAVCC:MGTAVCC_120  pwr
G5  GND:GND  pwr
G6  G:IO_G6
G7  G:IO_G7
G8  G:IO_G8
G9  G:IO_G9
G10  VCCO:VCCO24  pwr
G11  G:IO_G11
G12  G:IO_G12
G13  G:IO_G13
G14  G:IO_G14
G15  GND:GND  pwr
G16  G:IO_G16
G17  G:IO_G17
G18  G:IO_G18
G19  NC:NOCONNECT121  pas
G20  VCCO:VCCO7  pwr
G21  NC:NOCONNECT122  pas
G22  NC:NOCONNECT123  pas
G23  NC:NOCONNECT124  pas
G24  NC:NOCONNECT125  pas
G25  GND:GND  pwr
G26  NC:NOCONNECT126  pas
G27  G:IO_G27
G28  G:IO_G28
G29  G:IO_G29
G30  VCCO:VCCO31  pwr
G31  G:IO_G31
G32  G:IO_G32
G33  G:IO_G33
G34  G:IO_G34
G35  GND:GND  pwr
G36  G:IO_G36
G37  G:IO_G37
G38  G:IO_G38
G39  G:IO_G39
G40  VCCO:VCCO19  pwr
G41  G:IO_G41
G42  G:IO_G42
H1  MGRX:MGTRXP1_120  pas
H2  MGTTRXN:MGTTXN1_120  pas
H3  MGTAVCCPLL:MGTAVCCPLL_120  pwr
H4  GND:GND  pwr
H5  H:IO_H5
H6  H:IO_H6
H7  VCCO:VCCO24  pwr
H8  H:IO_H8
H9  H:IO_H9
H10  H:IO_H10
H11  H:IO_H11
H12  GND:GND  pwr
H13  H:IO_H13
H14  H:IO_H14
H15  H:IO_H15
H16  H:IO_H16
H17  VCCO:VCCO7  pwr
H18  H:IO_H18
H19  NC:NOCONNECT127  pas
H20  NC:NOCONNECT128  pas
H21  NC:NOCONNECT129  pas
H22  GND:GND  pwr
H23  NC:NOCONNECT130  pas
H24  NC:NOCONNECT131  pas
H25  NC:NOCONNECT132  pas
H26  H:IO_H26
H27  VCCO:VCCO3  pwr
H28  H:IO_H28
H29  H:IO_H29
H30  H:IO_H30
H31  H:IO_H31
H32  GND:GND  pwr
H33  H:IO_H33
H34  H:IO_H34
H35  H:IO_H35
H36  H:IO_H36
H37  VCCO:VCCO23  pwr
H38  H:IO_H38
H39  H:IO_H39
H40  H:IO_H40
H41  H:IO_H41
H42  GND:GND  pwr
J2  MGTTRXN:MGTTXP1_120  pas
J3  MGTAVTTRX:MGTAVTTTX_1202  pas
J4  GND:GND  pwr
J5  J:IO_J5
J6  J:IO_J6
J7  J:IO_J7
J8  J:IO_J8
J9  GND:GND  pwr
J10  J:IO_J10
J11  J:IO_J11
J12  J:IO_J12
J13  J:IO_J13
J14  VCCO:VCCO1  pwr
J15  J:IO_J15
J16  J:IO_J16
J17  J:IO_J17
J18  J:IO_J18
J19  GND:GND  pwr
J20  NC:NOCONNECT133  pas
J21  NC:NOCONNECT134  pas
J22  NC:NOCONNECT135  pas
J23  NC:NOCONNECT136  pas
J24  GND:GND  pwr
J25  J:IO_J25
J26  J:IO_J26
J27  J:IO_J27
J28  J:IO_J28
J29  GND:GND  pwr
J30  J:IO_J30
J31  J:IO_J31
J32  J:IO_J32
J33  J:IO_J33
J34  VCCO:VCCO27  pwr
J35  J:IO_J35
J36  J:IO_J36
J37  J:IO_J37
J38  J:IO_J38
J39  GND:GND  pwr
J40  J:IO_J40
J41  J:IO_J41
J42  J:IO_J42
K2  MGTTRXN:MGTTXP0_116  pas
K3  MGTAVTTRX:MGTAVTTTX_1161  pas
K4  K:IO_K4
K5  K:IO_K5
K6  GND:GND  pwr
K7  K:IO_K7
K8  K:IO_K8
K9  K:IO_K9
K10  K:IO_K10
K11  GND:GND  pwr
K12  K:IO_K12
K13  K:IO_K13
K14  K:IO_K14
K15  K:IO_K15
K16  GND:GND  pwr
K17  K:IO_K17
K18  K:IO_K18
K19  K:IO_K19
K20  NC:NOCONNECT137  pas
K21  GND:GND  pwr
K22  NC:NOCONNECT138  pas
K23  NC:NOCONNECT139  pas
K24  K:IO_K24
K25  K:IO_K25
K26  GND:GND  pwr
K27  K:IO_K27
K28  K:IO_K28
K29  K:IO_K29
K30  K:IO_K30
K31  GND:GND  pwr
K32  K:IO_K32
K33  K:IO_K33
K34  K:IO_K34
K35  K:IO_K35
K36  GND:GND  pwr
K37  K:IO_K37
K38  K:IO_K38
K39  K:IO_K39
K40  K:IO_K40
K41  VCCO:VCCO19  pwr
K42  K:IO_K42
L1  MGRX:MGTRXP0_116  pas
L2  MGTTRXN:MGTTXN0_116  pas
L3  MGTAVTTRX:MGTAVTTRX_116  pas
L4  GND:GND  pwr
L5  L:IO_L5
L6  L:IO_L6
L7  L:IO_L7
L8  VCCO:VCCO20  pwr
L9  L:IO_L9
L10  L:IO_L10
L11  L:IO_L11
L12  L:IO_L12
L13  GND:GND  pwr
L14  L:IO_L14
L15  L:IO_L15
L16  L:IO_L16
L17  L:IO_L17
L18  GND:GND  pwr
L19  L:IO_L19
L20  L:IO_L20
L21  NC:NOCONNECT140  pas
L22  NC:NOCONNECT141  pas
L23  GND:GND  pwr
L24  L:IO_L24
L25  L:IO_L25
L26  L:IO_L26
L27  L:IO_L27
L28  GND:GND  pwr
L29  L:IO_L29
L30  L:IO_L30
L31  L:IO_L31
L32  L:IO_L32
L33  GND:GND  pwr
L34  L:IO_L34
L35  L:IO_L35
L36  L:IO_L36
L37  L:IO_L37
L38  VCCO:VCCO19  pwr
L39  L:IO_L39
L40  L:IO_L40
L41  L:IO_L41
L42  L:IO_L42
M1  MGRX:MGTRXN0_116  pas
M2  GND:GND  pwr
M3  MGREFCLKN:MGTREFCLKN_116  pas
M4  MGREFCLKN:MGTREFCLKP_116  pas
M5  GND:GND  pwr
M6  M:IO_M6
M7  M:IO_M7
M8  M:IO_M8
M9  M:IO_M9
M10  GND:GND  pwr
M11  M:IO_M11
M12  M:IO_M12
M13  M:IO_M13
M14  M:IO_M14
M15  GND:GND  pwr
M16  M:IO_M16
M17  M:IO_M17
M18  M:IO_M18
M19  M:IO_M19
M20  GND:GND  pwr
M21  NC:NOCONNECT142  pas
M22  NC:NOCONNECT143  pas
M23  NC:NOCONNECT144  pas
M24  M:IO_M24
M25  GND:GND  pwr
M26  M:IO_M26
M27  M:IO_M27
M28  M:IO_M28
M29  M:IO_M29
M30  GND:GND  pwr
M31  M:IO_M31
M32  M:IO_M32
M33  M:IO_M33
M34  M:IO_M34
M35  GND:GND  pwr
M36  M:IO_M36
M37  M:IO_M37
M38  M:IO_M38
M39  M:IO_M39
M40  GND:GND  pwr
M41  M:IO_M41
M42  M:IO_M42
N1  MGRX:MGTRXN1_116  pas
N2  GND:GND  pwr
N3  MGTAVCC:MGTAVCC_116  pwr
N4  MGTAVCC:MGTAVCC_116  pwr
N5  N:IO_N5
N6  N:IO_N6
N7  GND:GND  pwr
N8  N:IO_N8
N9  N:IO_N9
N10  N:IO_N10
N11  N:IO_N11
N12  GND:GND  pwr
N13  N:IO_N13
N14  N:IO_N14
N15  N:IO_N15
N16  N:IO_N16
N17  GND:GND  pwr
N18  N:IO_N18
N19  N:IO_N19
N20  N:IO_N20
N21  NC:NOCONNECT145  pas
N22  NC:NOCONNECT146  pas
N23  NC:NOCONNECT147  pas
N24  NC:NOCONNECT148  pas
N25  N:IO_N25
N26  N:IO_N26
N27  GND:GND  pwr
N28  N:IO_N28
N29  N:IO_N29
N30  N:IO_N30
N31  N:IO_N31
N32  GND:GND  pwr
N33  N:IO_N33
N34  N:IO_N34
N35  N:IO_N35
N36  N:IO_N36
N37  GND:GND  pwr
N38  N:IO_N38
N39  N:IO_N39
N40  N:IO_N40
N41  N:IO_N41
N42  GND:GND  pwr
P1  MGRX:MGTRXP1_116  pas
P2  MGTTRXN:MGTTXN1_116  pas
P3  MGTAVCCPLL:MGTAVCCPLL_116  pwr
P4  GND:GND  pwr
P5  P:IO_P5
P6  P:IO_P6
P7  P:IO_P7
P8  P:IO_P8
P9  VCCO:VCCO20  pwr
P10  P:IO_P10
P11  P:IO_P11
P12  P:IO_P12
P13  P:IO_P13
P14  GND:GND  pwr
P15  A:HSWAP_EN_P15  in
P16  GND:GND  pwr
P17  P:IO_P17
P18  P:IO_P18
P19  GND:GND  pwr
P20  P:IO_P20
P21  VCCINT:VCCINT  pwr
P22  GND:GND  pwr
P23  VCCINT:VCCINT  pwr
P24  GND:GND  pwr
P25  P:IO_P25
P26  P:IO_P26
P27  P:IO_P27
P28  P:IO_P28
P29  GND:GND  pwr
P30  A:VBATT_P30  pas
P31  P:IO_P31
P32  P:IO_P32
P33  P:IO_P33
P34  GND:GND  pwr
P35  P:IO_P35
P36  P:IO_P36
P37  P:IO_P37
P38  P:IO_P38
P39  VCCO:VCCO15  pwr
P40  P:IO_P40
P41  P:IO_P41
P42  P:IO_P42
R2  MGTTRXN:MGTTXP1_116  pas
R3  MGTAVTTRX:MGTAVTTTX_1162  pas
R4  R:IO_R4
R5  R:IO_R5
R6  VCCO:VCCO20  pwr
R7  R:IO_R7
R8  R:IO_R8
R9  R:IO_R9
R10  R:IO_R10
R11  GND:GND  pwr
R12  VCCAUX:VCCAUX  pwr
R13  GND:GND  pwr
R14  A:DONE_R14
R15  A:D_IN_R15  in
R16  VCCINT:VCCINT  pwr
R17  GND:GND  pwr
R18  VCCINT:VCCINT  pwr
R19  GND:GND  pwr
R20  VCCINT:VCCINT  pwr
R21  GND:GND  pwr
R22  VCCINT:VCCINT  pwr
R23  GND:GND  pwr
R24  VCCINT:VCCINT  pwr
R25  GND:GND  pwr
R26  VCCINT:VCCINT  pwr
R27  GND:GND  pwr
R28  VCCINT:VCCINT  pwr
R29  A:PROG_B  in
R30  A:RDWR_B_R30  in
R31  GND:GND  pwr
R32  R:IO_R32
R33  R:IO_R33
R34  R:IO_R34
R35  R:IO_R35
R36  VCCO:VCCO15  pwr
R37  R:IO_R37
R38  R:IO_R38
R39  R:IO_R39
R40  R:IO_R40
R41  GND:GND  pwr
R42  R:IO_R42
T2  MGTTRXN:MGTTXP0_112  pas
T3  MGTAVTTRX:MGTAVTTTX_1121  pas
T4  T:IO_T4
T5  T:IO_T5
T6  T:IO_T6
T7  T:IO_T7
T8  GND:GND  pwr
T9  T:IO_T9
T10  T:IO_T10
T11  T:IO_T11
T12  GND:GND  pwr
T13  VCCAUX:VCCAUX  pwr
T14  A:INIT_B_T14
T15  VCCINT:VCCINT  pwr
T16  GND:GND  pwr
T17  VCCINT:VCCINT  pwr
T18  GND:GND  pwr
T19  VCCINT:VCCINT  pwr
T20  GND:GND  pwr
T21  VCCINT:VCCINT  pwr
T22  GND:GND  pwr
T23  VCCINT:VCCINT  pwr
T24  GND:GND  pwr
T25  VCCINT:VCCINT  pwr
T26  GND:GND  pwr
T27  VCCINT:VCCINT  pwr
T28  GND:GND  pwr
T29  VCCAUX:VCCAUX  pwr
T30  A:CS_B_T30  in
T31  T:IO_T31
T32  T:IO_T32
T33  GND:GND  pwr
T34  T:IO_T34
T35  T:IO_T35
T36  T:IO_T36
T37  T:IO_T37
T38  GND:GND  pwr
T39  T:IO_T39
T40  T:IO_T40
T41  T:IO_T41
T42  T:IO_T42
U1  MGRX:MGTRXP0_112  pas
U2  MGTTRXN:MGTTXN0_112  pas
U3  MGTAVTTRX:MGTAVTTRX_112  pas
U4  GND:GND  pwr
U5  GND:GND  pwr
U6  U:IO_U6
U7  U:IO_U7
U8  U:IO_U8
U9  U:IO_U9
U10  VCCO:VCCO12  pwr
U11  U:IO_U11
U12  VCCAUX:VCCAUX  pwr
U13  GND:GND  pwr
U14  VCCINT:VCCINT  pwr
U15  GND:GND  pwr
U16  VCCINT:VCCINT  pwr
U17  GND:GND  pwr
U18  VCCINT:VCCINT  pwr
U19  GND:GND  pwr
U20  VCCINT:VCCINT  pwr
U21  GND:GND  pwr
U22  VCCINT:VCCINT  pwr
U23  GND:GND  pwr
U24  VCCINT:VCCINT  pwr
U25  GND:GND  pwr
U26  VCCINT:VCCINT  pwr
U27  GND:GND  pwr
U28  VCCINT:VCCINT  pwr
U29  GND:GND  pwr
U30  VCCAUX:VCCAUX  pwr
U31  U:IO_U31
U32  U:IO_U32
U33  U:IO_U33
U34  U:IO_U34
U35  GND:GND  pwr
U36  U:IO_U36
U37  U:IO_U37
U38  U:IO_U38
U39  U:IO_U39
U40  VCCO:VCCO15  pwr
U41  U:IO_U41
U42  U:IO_U42
V1  MGRX:MGTRXN0_112  pas
V2  GND:GND  pwr
V3  MGREFCLKN:MGTREFCLKN_112  pas
V4  MGREFCLKN:MGTREFCLKP_112  pas
V5  V:IO_V5
V6  V:IO_V6
V7  VCCO:VCCO12  pwr
V8  V:IO_V8
V9  V:IO_V9
V10  V:IO_V10
V11  V:IO_V11
V12  GND:GND  pwr
V13  VCCINT:VCCINT  pwr
V14  GND:GND  pwr
V15  VCCINT:VCCINT  pwr
V16  GND:GND  pwr
V17  VCCINT:VCCINT  pwr
V18  GND:GND  pwr
V19  VCCINT:VCCINT  pwr
V20  GND:GND  pwr
V21  VCCINT:VCCINT  pwr
V22  GND:GND  pwr
V23  VCCINT:VCCINT  pwr
V24  GND:GND  pwr
V25  VCCINT:VCCINT  pwr
V26  GND:GND  pwr
V27  VCCINT:VCCINT  pwr
V28  GND:GND  pwr
V29  VCCINT:VCCINT  pwr
V30  GND:GND  pwr
V31  A:VFS_V31  pas
V32  GND:GND  pwr
V33  V:IO_V33
V34  V:IO_V34
V35  V:IO_V35
V36  V:IO_V36
V37  VCCO:VCCO11  pwr
V38  V:IO_V38
V39  V:IO_V39
V40  V:IO_V40
V41  V:IO_V41
V42  GND:GND  pwr
W1  MGRX:MGTRXN1_112  pas
W2  GND:GND  pwr
W3  MGTAVCC:MGTAVCC_112  pwr
W4  MGTAVCC:MGTAVCC_112  pwr
W5  W:IO_W5
W6  W:IO_W6
W7  W:IO_W7
W8  W:IO_W8
W9  GND:GND  pwr
W10  W:IO_W10
W11  W:IO_W11
W12  VCCAUX:VCCAUX  pwr
W13  GND:GND  pwr
W14  VCCINT:VCCINT  pwr
W15  GND:GND  pwr
W16  VCCINT:VCCINT  pwr
W17  GND:GND  pwr
W18  VCCINT:VCCINT  pwr
W19  GND:GND  pwr
W20  VCCINT:VCCINT  pwr
W21  GND:GND  pwr
W22  VCCINT:VCCINT  pwr
W23  GND:GND  pwr
W24  VCCINT:VCCINT  pwr
W25  GND:GND  pwr
W26  VCCINT:VCCINT  pwr
W27  GND:GND  pwr
W28  VCCINT:VCCINT  pwr
W29  GND:GND  pwr
W30  VCCAUX:VCCAUX  pwr
W31  GND:GND  pwr
W32  W:IO_W32
W33  W:IO_W33
W34  GND:GND  pwr
W35  W:IO_W35
W36  W:IO_W36
W37  W:IO_W37
W38  W:IO_W38
W39  GND:GND  pwr
W40  W:IO_W40
W41  W:IO_W41
W42  W:IO_W42
Y1  MGRX:MGTRXP1_112  pas
Y2  MGTTRXN:MGTTXN1_112  pas
Y3  MGTAVCCPLL:MGTAVCCPLL_112  pwr
Y4  GND:GND  pwr
Y5  NC:NOCONNECT149  pas
Y6  GND:GND  pwr
Y7  Y:IO_Y7
Y8  Y:IO_Y8
Y9  Y:IO_Y9
Y10  Y:IO_Y10
Y11  GND:GND  pwr
Y12  GND:GND  pwr
Y13  VCCINT:VCCINT  pwr
Y14  GND:GND  pwr
Y15  VCCINT:VCCINT  pwr
Y16  GND:GND  pwr
Y17  VCCINT:VCCINT  pwr
Y18  GND:GND  pwr
Y19  VCCINT:VCCINT  pwr
Y20  GND:GND  pwr
Y21  A:AVSS_Y21  pwr
Y22  A:AVDD_Y22  pwr
Y23  VCCINT:VCCINT  pwr
Y24  GND:GND  pwr
Y25  VCCINT:VCCINT  pwr
Y26  GND:GND  pwr
Y27  VCCINT:VCCINT  pwr
Y28  GND:GND  pwr
Y29  VCCINT:VCCINT  pwr
Y30  GND:GND  pwr
Y31  VCCAUX:VCCAUX  pwr
Y32  Y:IO_Y32
Y33  Y:IO_Y33
Y34  Y:IO_Y34
Y35  Y:IO_Y35
Y36  GND:GND  pwr
Y37  Y:IO_Y37
Y38  Y:IO_Y38
Y39  Y:IO_Y39
Y40  Y:IO_Y40
Y41  VCCO:VCCO11  pwr
Y42  Y:IO_Y42

## Footprint FF1738 (pad centres in mm)
xc5vlx110t_ff1738 edit this description Auto generated by make-symbol-device-package-bsdl.ulp Rev. 19 Source: xc5vlx110t_ff1738.bsd http://www.xilinx.com/support/documentation/package_specs/ff1738.pdf
smd 0.6 x 0.6: A2 -19.5,20.5; A3 -18.5,20.5; A4 -17.5,20.5; A5 -16.5,20.5; A8 -13.5,20.5; A9 -12.5,20.5; A10 -11.5,20.5; A11 -10.5,20.5; A14 -7.5,20.5; A15 -6.5,20.5; A16 -5.5,20.5; A17 -4.5,20.5; A19 -2.5,20.5; A20 -1.5,20.5; A21 -0.5,20.5; A22 0.5,20.5; A23 1.5,20.5; A24 2.5,20.5; A25 3.5,20.5; A26 4.5,20.5; A27 5.5,20.5; A28 6.5,20.5; A29 7.5,20.5; A30 8.5,20.5; A31 9.5,20.5; A32 10.5,20.5; A33 11.5,20.5; A34 12.5,20.5; A35 13.5,20.5; A36 14.5,20.5; A37 15.5,20.5; A38 16.5,20.5; A39 17.5,20.5; A40 18.5,20.5; A41 19.5,20.5; AA2 -19.5,0.5; AA3 -18.5,0.5; AA4 -17.5,0.5; AA5 -16.5,0.5; AA6 -15.5,0.5; AA7 -14.5,0.5; AA8 -13.5,0.5; AA9 -12.5,0.5; AA10 -11.5,0.5; AA11 -10.5,0.5; AA12 -9.5,0.5; AA13 -8.5,0.5; AA14 -7.5,0.5; AA15 -6.5,0.5; AA16 -5.5,0.5; AA17 -4.5,0.5; AA18 -3.5,0.5; AA19 -2.5,0.5; AA20 -1.5,0.5; AA21 -0.5,0.5; AA22 0.5,0.5; AA23 1.5,0.5; AA24 2.5,0.5; AA25 3.5,0.5; AA26 4.5,0.5; AA27 5.5,0.5; AA28 6.5,0.5; AA29 7.5,0.5; AA30 8.5,0.5; AA31 9.5,0.5; AA32 10.5,0.5; AA33 11.5,0.5; AA34 12.5,0.5; AA35 13.5,0.5; AA36 14.5,0.5; AA37 15.5,0.5; AA38 16.5,0.5; AA39 17.5,0.5; AA40 18.5,0.5; AA41 19.5,0.5; AA42 20.5,0.5; AB2 -19.5,-0.5; AB3 -18.5,-0.5; AB4 -17.5,-0.5; AB5 -16.5,-0.5; AB6 -15.5,-0.5; AB7 -14.5,-0.5; AB8 -13.5,-0.5; AB9 -12.5,-0.5; AB10 -11.5,-0.5; AB11 -10.5,-0.5; AB12 -9.5,-0.5; AB13 -8.5,-0.5; AB14 -7.5,-0.5; AB15 -6.5,-0.5; AB16 -5.5,-0.5; AB17 -4.5,-0.5; AB18 -3.5,-0.5; AB19 -2.5,-0.5; AB20 -1.5,-0.5; AB21 -0.5,-0.5; AB22 0.5,-0.5; AB23 1.5,-0.5; AB24 2.5,-0.5; AB25 3.5,-0.5; AB26 4.5,-0.5; AB27 5.5,-0.5; AB28 6.5,-0.5; AB29 7.5,-0.5; AB30 8.5,-0.5; AB31 9.5,-0.5; AB32 10.5,-0.5; AB33 11.5,-0.5; AB34 12.5,-0.5; AB35 13.5,-0.5; AB36 14.5,-0.5; AB37 15.5,-0.5; AB38 16.5,-0.5; AB39 17.5,-0.5; AB40 18.5,-0.5; AB41 19.5,-0.5; AB42 20.5,-0.5; AC1 -20.5,-1.5; AC2 -19.5,-1.5; AC3 -18.5,-1.5; AC4 -17.5,-1.5; AC5 -16.5,-1.5; AC6 -15.5,-1.5; AC7 -14.5,-1.5; AC8 -13.5,-1.5; AC9 -12.5,-1.5; AC10 -11.5,-1.5; AC11 -10.5,-1.5; AC12 -9.5,-1.5; AC13 -8.5,-1.5; AC14 -7.5,-1.5; AC15 -6.5,-1.5; AC16 -5.5,-1.5; AC17 -4.5,-1.5; AC18 -3.5,-1.5; AC19 -2.5,-1.5; AC20 -1.5,-1.5; AC21 -0.5,-1.5; AC22 0.5,-1.5; AC23 1.5,-1.5; AC24 2.5,-1.5; AC25 3.5,-1.5; AC26 4.5,-1.5; AC27 5.5,-1.5; AC28 6.5,-1.5; AC29 7.5,-1.5; AC30 8.5,-1.5; AC31 9.5,-1.5; AC32 10.5,-1.5; AC33 11.5,-1.5; AC34 12.5,-1.5; AC35 13.5,-1.5; AC36 14.5,-1.5; AC37 15.5,-1.5; AC38 16.5,-1.5; AC39 17.5,-1.5; AC40 18.5,-1.5; AC41 19.5,-1.5; AC42 20.5,-1.5; AD1 -20.5,-2.5; AD2 -19.5,-2.5; AD3 -18.5,-2.5; AD4 -17.5,-2.5; AD5 -16.5,-2.5; AD6 -15.5,-2.5; AD7 -14.5,-2.5; AD8 -13.5,-2.5; AD9 -12.5,-2.5; AD10 -11.5,-2.5; AD11 -10.5,-2.5; AD12 -9.5,-2.5; AD13 -8.5,-2.5; AD14 -7.5,-2.5; AD15 -6.5,-2.5; AD16 -5.5,-2.5; AD17 -4.5,-2.5; AD18 -3.5,-2.5; AD19 -2.5,-2.5; AD20 -1.5,-2.5; AD21 -0.5,-2.5; AD22 0.5,-2.5; AD23 1.5,-2.5; AD24 2.5,-2.5; AD25 3.5,-2.5; AD26 4.5,-2.5; AD27 5.5,-2.5; AD28 6.5,-2.5; AD29 7.5,-2.5; AD30 8.5,-2.5; AD31 9.5,-2.5; AD32 10.5,-2.5; AD33 11.5,-2.5; AD34 12.5,-2.5; AD35 13.5,-2.5; AD36 14.5,-2.5; AD37 15.5,-2.5; AD38 16.5,-2.5; AD39 17.5,-2.5; AD40 18.5,-2.5; AD41 19.5,-2.5; AD42 20.5,-2.5; AE1 -20.5,-3.5; AE2 -19.5,-3.5; AE3 -18.5,-3.5; AE4 -17.5,-3.5; AE5 -16.5,-3.5; AE6 -15.5,-3.5; AE7 -14.5,-3.5; AE8 -13.5,-3.5; AE9 -12.5,-3.5; AE10 -11.5,-3.5; AE11 -10.5,-3.5; AE12 -9.5,-3.5; AE13 -8.5,-3.5; AE14 -7.5,-3.5; AE15 -6.5,-3.5; AE16 -5.5,-3.5; AE17 -4.5,-3.5; AE18 -3.5,-3.5; AE19 -2.5,-3.5; AE20 -1.5,-3.5; AE21 -0.5,-3.5; AE22 0.5,-3.5; AE23 1.5,-3.5; AE24 2.5,-3.5; AE25 3.5,-3.5; AE26 4.5,-3.5; AE27 5.5,-3.5; AE28 6.5,-3.5; AE29 7.5,-3.5; AE30 8.5,-3.5; AE31 9.5,-3.5; AE32 10.5,-3.5; AE33 11.5,-3.5; AE34 12.5,-3.5; AE35 13.5,-3.5; AE36 14.5,-3.5; AE37 15.5,-3.5; AE38 16.5,-3.5; AE39 17.5,-3.5; AE40 18.5,-3.5; AE41 19.5,-3.5; AE42 20.5,-3.5; AF1 -20.5,-4.5; AF2 -19.5,-4.5; AF3 -18.5,-4.5; AF4 -17.5,-4.5; AF5 -16.5,-4.5; AF6 -15.5,-4.5; AF7 -14.5,-4.5; AF8 -13.5,-4.5; AF9 -12.5,-4.5; AF10 -11.5,-4.5; AF11 -10.5,-4.5; AF12 -9.5,-4.5; AF13 -8.5,-4.5; AF14 -7.5,-4.5; AF15 -6.5,-4.5; AF16 -5.5,-4.5; AF17 -4.5,-4.5; AF18 -3.5,-4.5; AF19 -2.5,-4.5; AF20 -1.5,-4.5; AF21 -0.5,-4.5; AF22 0.5,-4.5; AF23 1.5,-4.5; AF24 2.5,-4.5; AF25 3.5,-4.5; AF26 4.5,-4.5; AF27 5.5,-4.5; AF28 6.5,-4.5; AF29 7.5,-4.5; AF30 8.5,-4.5; AF31 9.5,-4.5; AF32 10.5,-4.5; AF33 11.5,-4.5; AF34 12.5,-4.5; AF35 13.5,-4.5; AF36 14.5,-4.5; AF37 15.5,-4.5; AF38 16.5,-4.5; AF39 17.5,-4.5; AF40 18.5,-4.5; AF41 19.5,-4.5; AF42 20.5,-4.5; AG2 -19.5,-5.5; AG3 -18.5,-5.5; AG4 -17.5,-5.5; AG5 -16.5,-5.5; AG6 -15.5,-5.5; AG7 -14.5,-5.5; AG8 -13.5,-5.5; AG9 -12.5,-5.5; AG10 -11.5,-5.5; AG11 -10.5,-5.5; AG12 -9.5,-5.5; AG13 -8.5,-5.5; AG14 -7.5,-5.5; AG15 -6.5,-5.5; AG16 -5.5,-5.5; AG17 -4.5,-5.5; AG18 -3.5,-5.5; AG19 -2.5,-5.5; AG20 -1.5,-5.5; AG21 -0.5,-5.5; AG22 0.5,-5.5; AG23 1.5,-5.5; AG24 2.5,-5.5; AG25 3.5,-5.5; AG26 4.5,-5.5; AG27 5.5,-5.5; AG28 6.5,-5.5; AG29 7.5,-5.5; AG30 8.5,-5.5; AG31 9.5,-5.5; AG32 10.5,-5.5; AG33 11.5,-5.5; AG34 12.5,-5.5; AG35 13.5,-5.5; AG36 14.5,-5.5; AG37 15.5,-5.5; AG38 16.5,-5.5; AG39 17.5,-5.5; AG40 18.5,-5.5; AG41 19.5,-5.5; AG42 20.5,-5.5; AH2 -19.5,-6.5; AH3 -18.5,-6.5; AH4 -17.5,-6.5; AH5 -16.5,-6.5; AH6 -15.5,-6.5; AH7 -14.5,-6.5; AH8 -13.5,-6.5; AH9 -12.5,-6.5; AH10 -11.5,-6.5; AH11 -10.5,-6.5; AH12 -9.5,-6.5; AH13 -8.5,-6.5; AH14 -7.5,-6.5; AH15 -6.5,-6.5; AH16 -5.5,-6.5; AH17 -4.5,-6.5; AH18 -3.5,-6.5; AH19 -2.5,-6.5; AH20 -1.5,-6.5; AH21 -0.5,-6.5; AH22 0.5,-6.5; AH23 1.5,-6.5; AH24 2.5,-6.5; AH25 3.5,-6.5; AH26 4.5,-6.5; AH27 5.5,-6.5; AH28 6.5,-6.5; AH29 7.5,-6.5; AH30 8.5,-6.5; AH31 9.5,-6.5; AH32 10.5,-6.5; AH33 11.5,-6.5; AH34 12.5,-6.5; AH35 13.5,-6.5; AH36 14.5,-6.5; AH37 15.5,-6.5; AH38 16.5,-6.5; AH39 17.5,-6.5; AH40 18.5,-6.5; AH41 19.5,-6.5; AH42 20.5,-6.5; AJ1 -20.5,-7.5; AJ2 -19.5,-7.5; AJ3 -18.5,-7.5; AJ4 -17.5,-7.5; AJ5 -16.5,-7.5; AJ6 -15.5,-7.5; AJ7 -14.5,-7.5; AJ8 -13.5,-7.5; AJ9 -12.5,-7.5; AJ10 -11.5,-7.5; AJ11 -10.5,-7.5; AJ12 -9.5,-7.5; AJ13 -8.5,-7.5; AJ14 -7.5,-7.5; AJ15 -6.5,-7.5; AJ16 -5.5,-7.5; AJ17 -4.5,-7.5; AJ18 -3.5,-7.5; AJ19 -2.5,-7.5; AJ20 -1.5,-7.5; AJ21 -0.5,-7.5; AJ22 0.5,-7.5; AJ23 1.5,-7.5; AJ24 2.5,-7.5; AJ25 3.5,-7.5; AJ26 4.5,-7.5; AJ27 5.5,-7.5; AJ28 6.5,-7.5; AJ29 7.5,-7.5; AJ30 8.5,-7.5; AJ31 9.5,-7.5; AJ32 10.5,-7.5; AJ33 11.5,-7.5; AJ34 12.5,-7.5; AJ35 13.5,-7.5; AJ36 14.5,-7.5; AJ37 15.5,-7.5; AJ38 16.5,-7.5; AJ39 17.5,-7.5; AJ40 18.5,-7.5; AJ41 19.5,-7.5; AJ42 20.5,-7.5; AK1 -20.5,-8.5; AK2 -19.5,-8.5; AK3 -18.5,-8.5; AK4 -17.5,-8.5; AK5 -16.5,-8.5; AK6 -15.5,-8.5; AK7 -14.5,-8.5; AK8 -13.5,-8.5; AK9 -12.5,-8.5; AK10 -11.5,-8.5; AK11 -10.5,-8.5; AK12 -9.5,-8.5; AK13 -8.5,-8.5; AK14 -7.5,-8.5; AK15 -6.5,-8.5; AK16 -5.5,-8.5; AK17 -4.5,-8.5; AK18 -3.5,-8.5; AK19 -2.5,-8.5; AK20 -1.5,-8.5; AK21 -0.5,-8.5; AK22 0.5,-8.5; AK23 1.5,-8.5; AK24 2.5,-8.5; AK25 3.5,-8.5; AK26 4.5,-8.5; AK27 5.5,-8.5; AK28 6.5,-8.5; AK29 7.5,-8.5; AK30 8.5,-8.5; AK31 9.5,-8.5; AK32 10.5,-8.5; AK33 11.5,-8.5; AK34 12.5,-8.5; AK35 13.5,-8.5; AK36 14.5,-8.5; AK37 15.5,-8.5; AK38 16.5,-8.5; AK39 17.5,-8.5; AK40 18.5,-8.5; AK41 19.5,-8.5; AK42 20.5,-8.5; AL1 -20.5,-9.5; AL2 -19.5,-9.5; AL3 -18.5,-9.5; AL4 -17.5,-9.5; AL5 -16.5,-9.5; AL6 -15.5,-9.5; AL7 -14.5,-9.5; AL8 -13.5,-9.5; AL9 -12.5,-9.5; AL10 -11.5,-9.5; AL11 -10.5,-9.5; AL12 -9.5,-9.5; AL13 -8.5,-9.5; AL14 -7.5,-9.5; AL15 -6.5,-9.5; AL16 -5.5,-9.5; AL17 -4.5,-9.5; AL18 -3.5,-9.5; AL19 -2.5,-9.5; AL20 -1.5,-9.5; AL21 -0.5,-9.5; AL22 0.5,-9.5; AL23 1.5,-9.5; AL24 2.5,-9.5; AL25 3.5,-9.5; AL26 4.5,-9.5; AL27 5.5,-9.5; AL28 6.5,-9.5; AL29 7.5,-9.5; AL30 8.5,-9.5; AL31 9.5,-9.5; AL32 10.5,-9.5; AL33 11.5,-9.5; AL34 12.5,-9.5; AL35 13.5,-9.5; AL36 14.5,-9.5; AL37 15.5,-9.5; AL38 16.5,-9.5; AL39 17.5,-9.5; AL40 18.5,-9.5; AL41 19.5,-9.5; AL42 20.5,-9.5; AM1 -20.5,-10.5; AM2 -19.5,-10.5; AM3 -18.5,-10.5; AM4 -17.5,-10.5; AM5 -16.5,-10.5; AM6 -15.5,-10.5; AM7 -14.5,-10.5; AM8 -13.5,-10.5; AM9 -12.5,-10.5; AM10 -11.5,-10.5; AM11 -10.5,-10.5; AM12 -9.5,-10.5; AM13 -8.5,-10.5; AM14 -7.5,-10.5; AM15 -6.5,-10.5; AM16 -5.5,-10.5; AM17 -4.5,-10.5; AM18 -3.5,-10.5; AM19 -2.5,-10.5; AM20 -1.5,-10.5; AM21 -0.5,-10.5; AM22 0.5,-10.5; AM23 1.5,-10.5; AM24 2.5,-10.5; AM25 3.5,-10.5; AM26 4.5,-10.5; AM27 5.5,-10.5; AM28 6.5,-10.5; AM29 7.5,-10.5; AM30 8.5,-10.5; AM31 9.5,-10.5; AM32 10.5,-10.5; AM33 11.5,-10.5; AM34 12.5,-10.5; AM35 13.5,-10.5; AM36 14.5,-10.5; AM37 15.5,-10.5; AM38 16.5,-10.5; AM39 17.5,-10.5; AM40 18.5,-10.5; AM41 19.5,-10.5; AM42 20.5,-10.5; AN2 -19.5,-11.5; AN3 -18.5,-11.5; AN4 -17.5,-11.5; AN5 -16.5,-11.5; AN6 -15.5,-11.5; AN7 -14.5,-11.5; AN8 -13.5,-11.5; AN9 -12.5,-11.5; AN10 -11.5,-11.5; AN11 -10.5,-11.5; AN12 -9.5,-11.5; AN13 -8.5,-11.5; AN14 -7.5,-11.5; AN15 -6.5,-11.5; AN16 -5.5,-11.5; AN17 -4.5,-11.5; AN18 -3.5,-11.5; AN19 -2.5,-11.5; AN20 -1.5,-11.5; AN21 -0.5,-11.5; AN22 0.5,-11.5; AN23 1.5,-11.5; AN24 2.5,-11.5; AN25 3.5,-11.5; AN26 4.5,-11.5; AN27 5.5,-11.5; AN28 6.5,-11.5; AN29 7.5,-11.5; AN30 8.5,-11.5; AN31 9.5,-11.5; AN32 10.5,-11.5; AN33 11.5,-11.5; AN34 12.5,-11.5; AN35 13.5,-11.5; AN36 14.5,-11.5; AN37 15.5,-11.5; AN38 16.5,-11.5; AN39 17.5,-11.5; AN40 18.5,-11.5; AN41 19.5,-11.5; AN42 20.5,-11.5; AP2 -19.5,-12.5; AP3 -18.5,-12.5; AP4 -17.5,-12.5; AP5 -16.5,-12.5; AP6 -15.5,-12.5; AP7 -14.5,-12.5; AP8 -13.5,-12.5; AP9 -12.5,-12.5; AP10 -11.5,-12.5; AP11 -10.5,-12.5; AP12 -9.5,-12.5; AP13 -8.5,-12.5; AP14 -7.5,-12.5; AP15 -6.5,-12.5; AP16 -5.5,-12.5; AP17 -4.5,-12.5; AP18 -3.5,-12.5; AP19 -2.5,-12.5; AP20 -1.5,-12.5; AP21 -0.5,-12.5; AP22 0.5,-12.5; AP23 1.5,-12.5; AP24 2.5,-12.5; AP25 3.5,-12.5; AP26 4.5,-12.5; AP27 5.5,-12.5; AP28 6.5,-12.5; AP29 7.5,-12.5; AP30 8.5,-12.5; AP31 9.5,-12.5; AP32 10.5,-12.5; AP33 11.5,-12.5; AP34 12.5,-12.5; AP35 13.5,-12.5; AP36 14.5,-12.5; AP37 15.5,-12.5; AP38 16.5,-12.5; AP39 17.5,-12.5; AP40 18.5,-12.5; AP41 19.5,-12.5; AP42 20.5,-12.5; AR1 -20.5,-13.5; AR2 -19.5,-13.5; AR3 -18.5,-13.5; AR4 -17.5,-13.5; AR5 -16.5,-13.5; AR6 -15.5,-13.5; AR7 -14.5,-13.5; AR8 -13.5,-13.5; AR9 -12.5,-13.5; AR10 -11.5,-13.5; AR11 -10.5,-13.5; AR12 -9.5,-13.5; AR13 -8.5,-13.5; AR14 -7.5,-13.5; AR15 -6.5,-13.5; AR16 -5.5,-13.5; AR17 -4.5,-13.5; AR18 -3.5,-13.5; AR19 -2.5,-13.5; AR20 -1.5,-13.5; AR21 -0.5,-13.5; AR22 0.5,-13.5; AR23 1.5,-13.5; AR24 2.5,-13.5; AR25 3.5,-13.5; AR26 4.5,-13.5; AR27 5.5,-13.5; AR28 6.5,-13.5; AR29 7.5,-13.5; AR30 8.5,-13.5; AR31 9.5,-13.5; AR32 10.5,-13.5; AR33 11.5,-13.5; AR34 12.5,-13.5; AR35 13.5,-13.5; AR36 14.5,-13.5; AR37 15.5,-13.5; AR38 16.5,-13.5; AR39 17.5,-13.5; AR40 18.5,-13.5; AR41 19.5,-13.5; AR42 20.5,-13.5; AT1 -20.5,-14.5; AT2 -19.5,-14.5; AT3 -18.5,-14.5; AT4 -17.5,-14.5; AT5 -16.5,-14.5; AT6 -15.5,-14.5; AT7 -14.5,-14.5; AT8 -13.5,-14.5; AT9 -12.5,-14.5; AT10 -11.5,-14.5; AT11 -10.5,-14.5; AT12 -9.5,-14.5; AT13 -8.5,-14.5; AT14 -7.5,-14.5; AT15 -6.5,-14.5; AT16 -5.5,-14.5; AT17 -4.5,-14.5; AT18 -3.5,-14.5; AT19 -2.5,-14.5; AT20 -1.5,-14.5; AT21 -0.5,-14.5; AT22 0.5,-14.5; AT23 1.5,-14.5; AT24 2.5,-14.5; AT25 3.5,-14.5; AT26 4.5,-14.5; AT27 5.5,-14.5; AT28 6.5,-14.5; AT29 7.5,-14.5; AT30 8.5,-14.5; AT31 9.5,-14.5; AT32 10.5,-14.5; AT33 11.5,-14.5; AT34 12.5,-14.5; AT35 13.5,-14.5; AT36 14.5,-14.5; AT37 15.5,-14.5; AT38 16.5,-14.5; AT39 17.5,-14.5; AT40 18.5,-14.5; AT41 19.5,-14.5; AT42 20.5,-14.5; AU1 -20.5,-15.5; AU2 -19.5,-15.5; AU3 -18.5,-15.5; AU4 -17.5,-15.5; AU5 -16.5,-15.5; AU6 -15.5,-15.5; AU7 -14.5,-15.5; AU8 -13.5,-15.5; AU9 -12.5,-15.5; AU10 -11.5,-15.5; AU11 -10.5,-15.5; AU12 -9.5,-15.5; AU13 -8.5,-15.5; AU14 -7.5,-15.5; AU15 -6.5,-15.5; AU16 -5.5,-15.5; AU17 -4.5,-15.5; AU18 -3.5,-15.5; AU19 -2.5,-15.5; AU20 -1.5,-15.5; AU21 -0.5,-15.5; AU22 0.5,-15.5; AU23 1.5,-15.5; AU24 2.5,-15.5; AU25 3.5,-15.5; AU26 4.5,-15.5; AU27 5.5,-15.5; AU28 6.5,-15.5; AU29 7.5,-15.5; AU30 8.5,-15.5; AU31 9.5,-15.5; AU32 10.5,-15.5; AU33 11.5,-15.5; AU34 12.5,-15.5; AU35 13.5,-15.5; AU36 14.5,-15.5; AU37 15.5,-15.5; AU38 16.5,-15.5; AU39 17.5,-15.5; AU40 18.5,-15.5; AU41 19.5,-15.5; AU42 20.5,-15.5; AV1 -20.5,-16.5; AV2 -19.5,-16.5; AV3 -18.5,-16.5; AV4 -17.5,-16.5; AV5 -16.5,-16.5; AV6 -15.5,-16.5; AV7 -14.5,-16.5; AV8 -13.5,-16.5; AV9 -12.5,-16.5; AV10 -11.5,-16.5; AV11 -10.5,-16.5; AV12 -9.5,-16.5; AV13 -8.5,-16.5; AV14 -7.5,-16.5; AV15 -6.5,-16.5; AV16 -5.5,-16.5; AV17 -4.5,-16.5; AV18 -3.5,-16.5; AV19 -2.5,-16.5; AV20 -1.5,-16.5; AV21 -0.5,-16.5; AV22 0.5,-16.5; AV23 1.5,-16.5; AV24 2.5,-16.5; AV25 3.5,-16.5; AV26 4.5,-16.5; AV27 5.5,-16.5; AV28 6.5,-16.5; AV29 7.5,-16.5; AV30 8.5,-16.5; AV31 9.5,-16.5; AV32 10.5,-16.5; AV33 11.5,-16.5; AV34 12.5,-16.5; AV35 13.5,-16.5; AV36 14.5,-16.5; AV37 15.5,-16.5; AV38 16.5,-16.5; AV39 17.5,-16.5; AV40 18.5,-16.5; AV41 19.5,-16.5; AV42 20.5,-16.5; AW2 -19.5,-17.5; AW3 -18.5,-17.5; AW4 -17.5,-17.5; AW5 -16.5,-17.5; AW6 -15.5,-17.5; AW7 -14.5,-17.5; AW8 -13.5,-17.5; AW9 -12.5,-17.5; AW10 -11.5,-17.5; AW11 -10.5,-17.5; AW12 -9.5,-17.5; AW13 -8.5,-17.5; AW14 -7.5,-17.5; AW15 -6.5,-17.5; AW16 -5.5,-17.5; AW17 -4.5,-17.5; AW18 -3.5,-17.5; AW19 -2.5,-17.5; AW20 -1.5,-17.5; AW21 -0.5,-17.5; AW22 0.5,-17.5; AW23 1.5,-17.5; AW24 2.5,-17.5; AW25 3.5,-17.5; AW26 4.5,-17.5; AW27 5.5,-17.5; AW28 6.5,-17.5; AW29 7.5,-17.5; AW30 8.5,-17.5; AW31 9.5,-17.5; AW32 10.5,-17.5; AW33 11.5,-17.5; AW34 12.5,-17.5; AW35 13.5,-17.5; AW36 14.5,-17.5; AW37 15.5,-17.5; AW38 16.5,-17.5; AW39 17.5,-17.5; AW40 18.5,-17.5; AW41 19.5,-17.5; AW42 20.5,-17.5; AY1 -20.5,-18.5; AY2 -19.5,-18.5; AY3 -18.5,-18.5; AY4 -17.5,-18.5; AY5 -16.5,-18.5; AY6 -15.5,-18.5; AY7 -14.5,-18.5; AY8 -13.5,-18.5; AY9 -12.5,-18.5; AY10 -11.5,-18.5; AY11 -10.5,-18.5; AY12 -9.5,-18.5; AY13 -8.5,-18.5; AY14 -7.5,-18.5; AY15 -6.5,-18.5; AY16 -5.5,-18.5; AY17 -4.5,-18.5; AY18 -3.5,-18.5; AY19 -2.5,-18.5; AY20 -1.5,-18.5; AY21 -0.5,-18.5; AY22 0.5,-18.5; AY23 1.5,-18.5; AY24 2.5,-18.5; AY25 3.5,-18.5; AY26 4.5,-18.5; AY27 5.5,-18.5; AY28 6.5,-18.5; AY29 7.5,-18.5; AY30 8.5,-18.5; AY31 9.5,-18.5; AY32 10.5,-18.5; AY33 11.5,-18.5; AY34 12.5,-18.5; AY35 13.5,-18.5; AY36 14.5,-18.5; AY37 15.5,-18.5; AY38 16.5,-18.5; AY39 17.5,-18.5; AY40 18.5,-18.5; AY41 19.5,-18.5; AY42 20.5,-18.5; B1 -20.5,19.5; B2 -19.5,19.5; B3 -18.5,19.5; B4 -17.5,19.5; B5 -16.5,19.5; B6 -15.5,19.5; B7 -14.5,19.5; B8 -13.5,19.5; B9 -12.5,19.5; B10 -11.5,19.5; B11 -10.5,19.5; B12 -9.5,19.5; B13 -8.5,19.5; B14 -7.5,19.5; B15 -6.5,19.5; B16 -5.5,19.5; B17 -4.5,19.5; B18 -3.5,19.5; B19 -2.5,19.5; B20 -1.5,19.5; B21 -0.5,19.5; B22 0.5,19.5; B23 1.5,19.5; B24 2.5,19.5; B25 3.5,19.5; B26 4.5,19.5; B27 5.5,19.5; B28 6.5,19.5; B29 7.5,19.5; B30 8.5,19.5; B31 9.5,19.5; B32 10.5,19.5; B33 11.5,19.5; B34 12.5,19.5; B35 13.5,19.5; B36 14.5,19.5; B37 15.5,19.5; B38 16.5,19.5; B39 17.5,19.5; B40 18.5,19.5; B41 19.5,19.5; B42 20.5,19.5; BA1 -20.5,-19.5; BA2 -19.5,-19.5; BA3 -18.5,-19.5; BA4 -17.5,-19.5; BA5 -16.5,-19.5; BA6 -15.5,-19.5; BA7 -14.5,-19.5; BA8 -13.5,-19.5; BA9 -12.5,-19.5; BA10 -11.5,-19.5; BA11 -10.5,-19.5; BA12 -9.5,-19.5; BA13 -8.5,-19.5; BA14 -7.5,-19.5; BA15 -6.5,-19.5; BA16 -5.5,-19.5; BA17 -4.5,-19.5; BA18 -3.5,-19.5; BA19 -2.5,-19.5; BA20 -1.5,-19.5; BA21 -0.5,-19.5; BA22 0.5,-19.5; BA23 1.5,-19.5; BA24 2.5,-19.5; BA25 3.5,-19.5; BA26 4.5,-19.5; BA27 5.5,-19.5; BA28 6.5,-19.5; BA29 7.5,-19.5; BA30 8.5,-19.5; BA31 9.5,-19.5; BA32 10.5,-19.5; BA33 11.5,-19.5; BA34 12.5,-19.5; BA35 13.5,-19.5; BA36 14.5,-19.5; BA37 15.5,-19.5; BA38 16.5,-19.5; BA39 17.5,-19.5; BA40 18.5,-19.5; BA41 19.5,-19.5; BA42 20.5,-19.5; BB2 -19.5,-20.5; BB3 -18.5,-20.5; BB4 -17.5,-20.5; BB5 -16.5,-20.5; BB8 -13.5,-20.5; BB9 -12.5,-20.5; BB10 -11.5,-20.5; BB11 -10.5,-20.5; BB14 -7.5,-20.5; BB15 -6.5,-20.5; BB16 -5.5,-20.5; BB17 -4.5,-20.5; BB19 -2.5,-20.5; BB20 -1.5,-20.5; BB21 -0.5,-20.5; BB22 0.5,-20.5; BB23 1.5,-20.5; BB24 2.5,-20.5; BB25 3.5,-20.5; BB26 4.5,-20.5; BB27 5.5,-20.5; BB28 6.5,-20.5; BB29 7.5,-20.5; BB30 8.5,-20.5; BB31 9.5,-20.5; BB32 10.5,-20.5; BB33 11.5,-20.5; BB34 12.5,-20.5; BB35 13.5,-20.5; BB36 14.5,-20.5; BB37 15.5,-20.5; BB38 16.5,-20.5; BB39 17.5,-20.5; BB40 18.5,-20.5; BB41 19.5,-20.5; C1 -20.5,18.5; C2 -19.5,18.5; C3 -18.5,18.5; C4 -17.5,18.5; C5 -16.5,18.5; C6 -15.5,18.5; C7 -14.5,18.5; C8 -13.5,18.5; C9 -12.5,18.5; C10 -11.5,18.5; C11 -10.5,18.5; C12 -9.5,18.5; C13 -8.5,18.5; C14 -7.5,18.5; C15 -6.5,18.5; C16 -5.5,18.5; C17 -4.5,18.5; C18 -3.5,18.5; C19 -2.5,18.5; C20 -1.5,18.5; C21 -0.5,18.5; C22 0.5,18.5; C23 1.5,18.5; C24 2.5,18.5; C25 3.5,18.5; C26 4.5,18.5; C27 5.5,18.5; C28 6.5,18.5; C29 7.5,18.5; C30 8.5,18.5; C31 9.5,18.5; C32 10.5,18.5; C33 11.5,18.5; C34 12.5,18.5; C35 13.5,18.5; C36 14.5,18.5; C37 15.5,18.5; C38 16.5,18.5; C39 17.5,18.5; C40 18.5,18.5; C41 19.5,18.5; C42 20.5,18.5; D2 -19.5,17.5; D3 -18.5,17.5; D4 -17.5,17.5; D5 -16.5,17.5; D6 -15.5,17.5; D7 -14.5,17.5; D8 -13.5,17.5; D9 -12.5,17.5; D10 -11.5,17.5; D11 -10.5,17.5; D12 -9.5,17.5; D13 -8.5,17.5; D14 -7.5,17.5; D15 -6.5,17.5; D16 -5.5,17.5; D17 -4.5,17.5; D18 -3.5,17.5; D19 -2.5,17.5; D20 -1.5,17.5; D21 -0.5,17.5; D22 0.5,17.5; D23 1.5,17.5; D24 2.5,17.5; D25 3.5,17.5; D26 4.5,17.5; D27 5.5,17.5; D28 6.5,17.5; D29 7.5,17.5; D30 8.5,17.5; D31 9.5,17.5; D32 10.5,17.5; D33 11.5,17.5; D34 12.5,17.5; D35 13.5,17.5; D36 14.5,17.5; D37 15.5,17.5; D38 16.5,17.5; D39 17.5,17.5; D40 18.5,17.5; D41 19.5,17.5; D42 20.5,17.5; E1 -20.5,16.5; E2 -19.5,16.5; E3 -18.5,16.5; E4 -17.5,16.5; E5 -16.5,16.5; E6 -15.5,16.5; E7 -14.5,16.5; E8 -13.5,16.5; E9 -12.5,16.5; E10 -11.5,16.5; E11 -10.5,16.5; E12 -9.5,16.5; E13 -8.5,16.5; E14 -7.5,16.5; E15 -6.5,16.5; E16 -5.5,16.5; E17 -4.5,16.5; E18 -3.5,16.5; E19 -2.5,16.5; E20 -1.5,16.5; E21 -0.5,16.5; E22 0.5,16.5; E23 1.5,16.5; E24 2.5,16.5; E25 3.5,16.5; E26 4.5,16.5; E27 5.5,16.5; E28 6.5,16.5; E29 7.5,16.5; E30 8.5,16.5; E31 9.5,16.5; E32 10.5,16.5; E33 11.5,16.5; E34 12.5,16.5; E35 13.5,16.5; E36 14.5,16.5; E37 15.5,16.5; E38 16.5,16.5; E39 17.5,16.5; E40 18.5,16.5; E41 19.5,16.5; E42 20.5,16.5; F1 -20.5,15.5; F2 -19.5,15.5; F3 -18.5,15.5; F4 -17.5,15.5; F5 -16.5,15.5; F6 -15.5,15.5; F7 -14.5,15.5; F8 -13.5,15.5; F9 -12.5,15.5; F10 -11.5,15.5; F11 -10.5,15.5; F12 -9.5,15.5; F13 -8.5,15.5; F14 -7.5,15.5; F15 -6.5,15.5; F16 -5.5,15.5; F17 -4.5,15.5; F18 -3.5,15.5; F19 -2.5,15.5; F20 -1.5,15.5; F21 -0.5,15.5; F22 0.5,15.5; F23 1.5,15.5; F24 2.5,15.5; F25 3.5,15.5; F26 4.5,15.5; F27 5.5,15.5; F28 6.5,15.5; F29 7.5,15.5; F30 8.5,15.5; F31 9.5,15.5; F32 10.5,15.5; F33 11.5,15.5; F34 12.5,15.5; F35 13.5,15.5; F36 14.5,15.5; F37 15.5,15.5; F38 16.5,15.5; F39 17.5,15.5; F40 18.5,15.5; F41 19.5,15.5; F42 20.5,15.5; G1 -20.5,14.5; G2 -19.5,14.5; G3 -18.5,14.5; G4 -17.5,14.5; G5 -16.5,14.5; G6 -15.5,14.5; G7 -14.5,14.5; G8 -13.5,14.5; G9 -12.5,14.5; G10 -11.5,14.5; G11 -10.5,14.5; G12 -9.5,14.5; G13 -8.5,14.5; G14 -7.5,14.5; G15 -6.5,14.5; G16 -5.5,14.5; G17 -4.5,14.5; G18 -3.5,14.5; G19 -2.5,14.5; G20 -1.5,14.5; G21 -0.5,14.5; G22 0.5,14.5; G23 1.5,14.5; G24 2.5,14.5; G25 3.5,14.5; G26 4.5,14.5; G27 5.5,14.5; G28 6.5,14.5; G29 7.5,14.5; G30 8.5,14.5; G31 9.5,14.5; G32 10.5,14.5; G33 11.5,14.5; G34 12.5,14.5; G35 13.5,14.5; G36 14.5,14.5; G37 15.5,14.5; G38 16.5,14.5; G39 17.5,14.5; G40 18.5,14.5; G41 19.5,14.5; G42 20.5,14.5; H1 -20.5,13.5; H2 -19.5,13.5; H3 -18.5,13.5; H4 -17.5,13.5; H5 -16.5,13.5; H6 -15.5,13.5; H7 -14.5,13.5; H8 -13.5,13.5; H9 -12.5,13.5; H10 -11.5,13.5; H11 -10.5,13.5; H12 -9.5,13.5; H13 -8.5,13.5; H14 -7.5,13.5; H15 -6.5,13.5; H16 -5.5,13.5; H17 -4.5,13.5; H18 -3.5,13.5; H19 -2.5,13.5; H20 -1.5,13.5; H21 -0.5,13.5; H22 0.5,13.5; H23 1.5,13.5; H24 2.5,13.5; H25 3.5,13.5; H26 4.5,13.5; H27 5.5,13.5; H28 6.5,13.5; H29 7.5,13.5; H30 8.5,13.5; H31 9.5,13.5; H32 10.5,13.5; H33 11.5,13.5; H34 12.5,13.5; H35 13.5,13.5; H36 14.5,13.5; H37 15.5,13.5; H38 16.5,13.5; H39 17.5,13.5; H40 18.5,13.5; H41 19.5,13.5; H42 20.5,13.5; J2 -19.5,12.5; J3 -18.5,12.5; J4 -17.5,12.5; J5 -16.5,12.5; J6 -15.5,12.5; J7 -14.5,12.5; J8 -13.5,12.5; J9 -12.5,12.5; J10 -11.5,12.5; J11 -10.5,12.5; J12 -9.5,12.5; J13 -8.5,12.5; J14 -7.5,12.5; J15 -6.5,12.5; J16 -5.5,12.5; J17 -4.5,12.5; J18 -3.5,12.5; J19 -2.5,12.5; J20 -1.5,12.5; J21 -0.5,12.5; J22 0.5,12.5; J23 1.5,12.5; J24 2.5,12.5; J25 3.5,12.5; J26 4.5,12.5; J27 5.5,12.5; J28 6.5,12.5; J29 7.5,12.5; J30 8.5,12.5; J31 9.5,12.5; J32 10.5,12.5; J33 11.5,12.5; J34 12.5,12.5; J35 13.5,12.5; J36 14.5,12.5; J37 15.5,12.5; J38 16.5,12.5; J39 17.5,12.5; J40 18.5,12.5; J41 19.5,12.5; J42 20.5,12.5; K2 -19.5,11.5; K3 -18.5,11.5; K4 -17.5,11.5; K5 -16.5,11.5; K6 -15.5,11.5; K7 -14.5,11.5; K8 -13.5,11.5; K9 -12.5,11.5; K10 -11.5,11.5; K11 -10.5,11.5; K12 -9.5,11.5; K13 -8.5,11.5; K14 -7.5,11.5; K15 -6.5,11.5; K16 -5.5,11.5; K17 -4.5,11.5; K18 -3.5,11.5; K19 -2.5,11.5; K20 -1.5,11.5; K21 -0.5,11.5; K22 0.5,11.5; K23 1.5,11.5; K24 2.5,11.5; K25 3.5,11.5; K26 4.5,11.5; K27 5.5,11.5; K28 6.5,11.5; K29 7.5,11.5; K30 8.5,11.5; K31 9.5,11.5; K32 10.5,11.5; K33 11.5,11.5; K34 12.5,11.5; K35 13.5,11.5; K36 14.5,11.5; K37 15.5,11.5; K38 16.5,11.5; K39 17.5,11.5; K40 18.5,11.5; K41 19.5,11.5; K42 20.5,11.5; L1 -20.5,10.5; L2 -19.5,10.5; L3 -18.5,10.5; L4 -17.5,10.5; L5 -16.5,10.5; L6 -15.5,10.5; L7 -14.5,10.5; L8 -13.5,10.5; L9 -12.5,10.5; L10 -11.5,10.5; L11 -10.5,10.5; L12 -9.5,10.5; L13 -8.5,10.5; L14 -7.5,10.5; L15 -6.5,10.5; L16 -5.5,10.5; L17 -4.5,10.5; L18 -3.5,10.5; L19 -2.5,10.5; L20 -1.5,10.5; L21 -0.5,10.5; L22 0.5,10.5; L23 1.5,10.5; L24 2.5,10.5; L25 3.5,10.5; L26 4.5,10.5; L27 5.5,10.5; L28 6.5,10.5; L29 7.5,10.5; L30 8.5,10.5; L31 9.5,10.5; L32 10.5,10.5; L33 11.5,10.5; L34 12.5,10.5; L35 13.5,10.5; L36 14.5,10.5; L37 15.5,10.5; L38 16.5,10.5; L39 17.5,10.5; L40 18.5,10.5; L41 19.5,10.5; L42 20.5,10.5; M1 -20.5,9.5; M2 -19.5,9.5; M3 -18.5,9.5; M4 -17.5,9.5; M5 -16.5,9.5; M6 -15.5,9.5; M7 -14.5,9.5; M8 -13.5,9.5; M9 -12.5,9.5; M10 -11.5,9.5; M11 -10.5,9.5; M12 -9.5,9.5; M13 -8.5,9.5; M14 -7.5,9.5; M15 -6.5,9.5; M16 -5.5,9.5; M17 -4.5,9.5; M18 -3.5,9.5; M19 -2.5,9.5; M20 -1.5,9.5; M21 -0.5,9.5; M22 0.5,9.5; M23 1.5,9.5; M24 2.5,9.5; M25 3.5,9.5; M26 4.5,9.5; M27 5.5,9.5; M28 6.5,9.5; M29 7.5,9.5; M30 8.5,9.5; M31 9.5,9.5; M32 10.5,9.5; M33 11.5,9.5; M34 12.5,9.5; M35 13.5,9.5; M36 14.5,9.5; M37 15.5,9.5; M38 16.5,9.5; M39 17.5,9.5; M40 18.5,9.5; M41 19.5,9.5; M42 20.5,9.5; N1 -20.5,8.5; N2 -19.5,8.5; N3 -18.5,8.5; N4 -17.5,8.5; N5 -16.5,8.5; N6 -15.5,8.5; N7 -14.5,8.5; N8 -13.5,8.5; N9 -12.5,8.5; N10 -11.5,8.5; N11 -10.5,8.5; N12 -9.5,8.5; N13 -8.5,8.5; N14 -7.5,8.5; N15 -6.5,8.5; N16 -5.5,8.5; N17 -4.5,8.5; N18 -3.5,8.5; N19 -2.5,8.5; N20 -1.5,8.5; N21 -0.5,8.5; N22 0.5,8.5; N23 1.5,8.5; N24 2.5,8.5; N25 3.5,8.5; N26 4.5,8.5; N27 5.5,8.5; N28 6.5,8.5; N29 7.5,8.5; N30 8.5,8.5; N31 9.5,8.5; N32 10.5,8.5; N33 11.5,8.5; N34 12.5,8.5; N35 13.5,8.5; N36 14.5,8.5; N37 15.5,8.5; N38 16.5,8.5; N39 17.5,8.5; N40 18.5,8.5; N41 19.5,8.5; N42 20.5,8.5; P1 -20.5,7.5; P2 -19.5,7.5; P3 -18.5,7.5; P4 -17.5,7.5; P5 -16.5,7.5; P6 -15.5,7.5; P7 -14.5,7.5; P8 -13.5,7.5; P9 -12.5,7.5; P10 -11.5,7.5; P11 -10.5,7.5; P12 -9.5,7.5; P13 -8.5,7.5; P14 -7.5,7.5; P15 -6.5,7.5; P16 -5.5,7.5; P17 -4.5,7.5; P18 -3.5,7.5; P19 -2.5,7.5; P20 -1.5,7.5; P21 -0.5,7.5; P22 0.5,7.5; P23 1.5,7.5; P24 2.5,7.5; P25 3.5,7.5; P26 4.5,7.5; P27 5.5,7.5; P28 6.5,7.5; P29 7.5,7.5; P30 8.5,7.5; P31 9.5,7.5; P32 10.5,7.5; P33 11.5,7.5; P34 12.5,7.5; P35 13.5,7.5; P36 14.5,7.5; P37 15.5,7.5; P38 16.5,7.5; P39 17.5,7.5; P40 18.5,7.5; P41 19.5,7.5; P42 20.5,7.5; R2 -19.5,6.5; R3 -18.5,6.5; R4 -17.5,6.5; R5 -16.5,6.5; R6 -15.5,6.5; R7 -14.5,6.5; R8 -13.5,6.5; R9 -12.5,6.5; R10 -11.5,6.5; R11 -10.5,6.5; R12 -9.5,6.5; R13 -8.5,6.5; R14 -7.5,6.5; R15 -6.5,6.5; R16 -5.5,6.5; R17 -4.5,6.5; R18 -3.5,6.5; R19 -2.5,6.5; R20 -1.5,6.5; R21 -0.5,6.5; R22 0.5,6.5; R23 1.5,6.5; R24 2.5,6.5; R25 3.5,6.5; R26 4.5,6.5; R27 5.5,6.5; R28 6.5,6.5; R29 7.5,6.5; R30 8.5,6.5; R31 9.5,6.5; R32 10.5,6.5; R33 11.5,6.5; R34 12.5,6.5; R35 13.5,6.5; R36 14.5,6.5; R37 15.5,6.5; R38 16.5,6.5; R39 17.5,6.5; R40 18.5,6.5; R41 19.5,6.5; R42 20.5,6.5; T2 -19.5,5.5; T3 -18.5,5.5; T4 -17.5,5.5; T5 -16.5,5.5; T6 -15.5,5.5; T7 -14.5,5.5; T8 -13.5,5.5; T9 -12.5,5.5; T10 -11.5,5.5; T11 -10.5,5.5; T12 -9.5,5.5; T13 -8.5,5.5; T14 -7.5,5.5; T15 -6.5,5.5; T16 -5.5,5.5; T17 -4.5,5.5; T18 -3.5,5.5; T19 -2.5,5.5; T20 -1.5,5.5; T21 -0.5,5.5; T22 0.5,5.5; T23 1.5,5.5; T24 2.5,5.5; T25 3.5,5.5; T26 4.5,5.5; T27 5.5,5.5; T28 6.5,5.5; T29 7.5,5.5; T30 8.5,5.5; T31 9.5,5.5; T32 10.5,5.5; T33 11.5,5.5; T34 12.5,5.5; T35 13.5,5.5; T36 14.5,5.5; T37 15.5,5.5; T38 16.5,5.5; T39 17.5,5.5; T40 18.5,5.5; T41 19.5,5.5; T42 20.5,5.5; U1 -20.5,4.5; U2 -19.5,4.5; U3 -18.5,4.5; U4 -17.5,4.5; U5 -16.5,4.5; U6 -15.5,4.5; U7 -14.5,4.5; U8 -13.5,4.5; U9 -12.5,4.5; U10 -11.5,4.5; U11 -10.5,4.5; U12 -9.5,4.5; U13 -8.5,4.5; U14 -7.5,4.5; U15 -6.5,4.5; U16 -5.5,4.5; U17 -4.5,4.5; U18 -3.5,4.5; U19 -2.5,4.5; U20 -1.5,4.5; U21 -0.5,4.5; U22 0.5,4.5; U23 1.5,4.5; U24 2.5,4.5; U25 3.5,4.5; U26 4.5,4.5; U27 5.5,4.5; U28 6.5,4.5; U29 7.5,4.5; U30 8.5,4.5; U31 9.5,4.5; U32 10.5,4.5; U33 11.5,4.5; U34 12.5,4.5; U35 13.5,4.5; U36 14.5,4.5; U37 15.5,4.5; U38 16.5,4.5; U39 17.5,4.5; U40 18.5,4.5; U41 19.5,4.5; U42 20.5,4.5; V1 -20.5,3.5; V2 -19.5,3.5; V3 -18.5,3.5; V4 -17.5,3.5; V5 -16.5,3.5; V6 -15.5,3.5; V7 -14.5,3.5; V8 -13.5,3.5; V9 -12.5,3.5; V10 -11.5,3.5; V11 -10.5,3.5; V12 -9.5,3.5; V13 -8.5,3.5; V14 -7.5,3.5; V15 -6.5,3.5; V16 -5.5,3.5; V17 -4.5,3.5; V18 -3.5,3.5; V19 -2.5,3.5; V20 -1.5,3.5; V21 -0.5,3.5; V22 0.5,3.5; V23 1.5,3.5; V24 2.5,3.5; V25 3.5,3.5; V26 4.5,3.5; V27 5.5,3.5; V28 6.5,3.5; V29 7.5,3.5; V30 8.5,3.5; V31 9.5,3.5; V32 10.5,3.5; V33 11.5,3.5; V34 12.5,3.5; V35 13.5,3.5; V36 14.5,3.5; V37 15.5,3.5; V38 16.5,3.5; V39 17.5,3.5; V40 18.5,3.5; V41 19.5,3.5; V42 20.5,3.5; W1 -20.5,2.5; W2 -19.5,2.5; W3 -18.5,2.5; W4 -17.5,2.5; W5 -16.5,2.5; W6 -15.5,2.5; W7 -14.5,2.5; W8 -13.5,2.5; W9 -12.5,2.5; W10 -11.5,2.5; W11 -10.5,2.5; W12 -9.5,2.5; W13 -8.5,2.5; W14 -7.5,2.5; W15 -6.5,2.5; W16 -5.5,2.5; W17 -4.5,2.5; W18 -3.5,2.5; W19 -2.5,2.5; W20 -1.5,2.5; W21 -0.5,2.5; W22 0.5,2.5; W23 1.5,2.5; W24 2.5,2.5; W25 3.5,2.5; W26 4.5,2.5; W27 5.5,2.5; W28 6.5,2.5; W29 7.5,2.5; W30 8.5,2.5; W31 9.5,2.5; W32 10.5,2.5; W33 11.5,2.5; W34 12.5,2.5; W35 13.5,2.5; W36 14.5,2.5; W37 15.5,2.5; W38 16.5,2.5; W39 17.5,2.5; W40 18.5,2.5; W41 19.5,2.5; W42 20.5,2.5; Y1 -20.5,1.5; Y2 -19.5,1.5; Y3 -18.5,1.5; Y4 -17.5,1.5; Y5 -16.5,1.5; Y6 -15.5,1.5; Y7 -14.5,1.5; Y8 -13.5,1.5; Y9 -12.5,1.5; Y10 -11.5,1.5; Y11 -10.5,1.5; Y12 -9.5,1.5; Y13 -8.5,1.5; Y14 -7.5,1.5; Y15 -6.5,1.5; Y16 -5.5,1.5; Y17 -4.5,1.5; Y18 -3.5,1.5; Y19 -2.5,1.5; Y20 -1.5,1.5; Y21 -0.5,1.5; Y22 0.5,1.5; Y23 1.5,1.5; Y24 2.5,1.5; Y25 3.5,1.5; Y26 4.5,1.5; Y27 5.5,1.5; Y28 6.5,1.5; Y29 7.5,1.5; Y30 8.5,1.5; Y31 9.5,1.5; Y32 10.5,1.5; Y33 11.5,1.5; Y34 12.5,1.5; Y35 13.5,1.5; Y36 14.5,1.5; Y37 15.5,1.5; Y38 16.5,1.5; Y39 17.5,1.5; Y40 18.5,1.5; Y41 19.5,1.5; Y42 20.5,1.5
